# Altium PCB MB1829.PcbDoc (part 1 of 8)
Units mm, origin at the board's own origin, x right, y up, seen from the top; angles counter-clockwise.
Board outline 90 x 110 mm, 6 copper layers (Top Layer, Signal Layer 1, Signal Layer 2, Signal Layer 3, Signal Layer 4, Bottom Layer), stack 1.578 mm thick; 466 components, 354 nets, 2058 pads, 1522 vias.
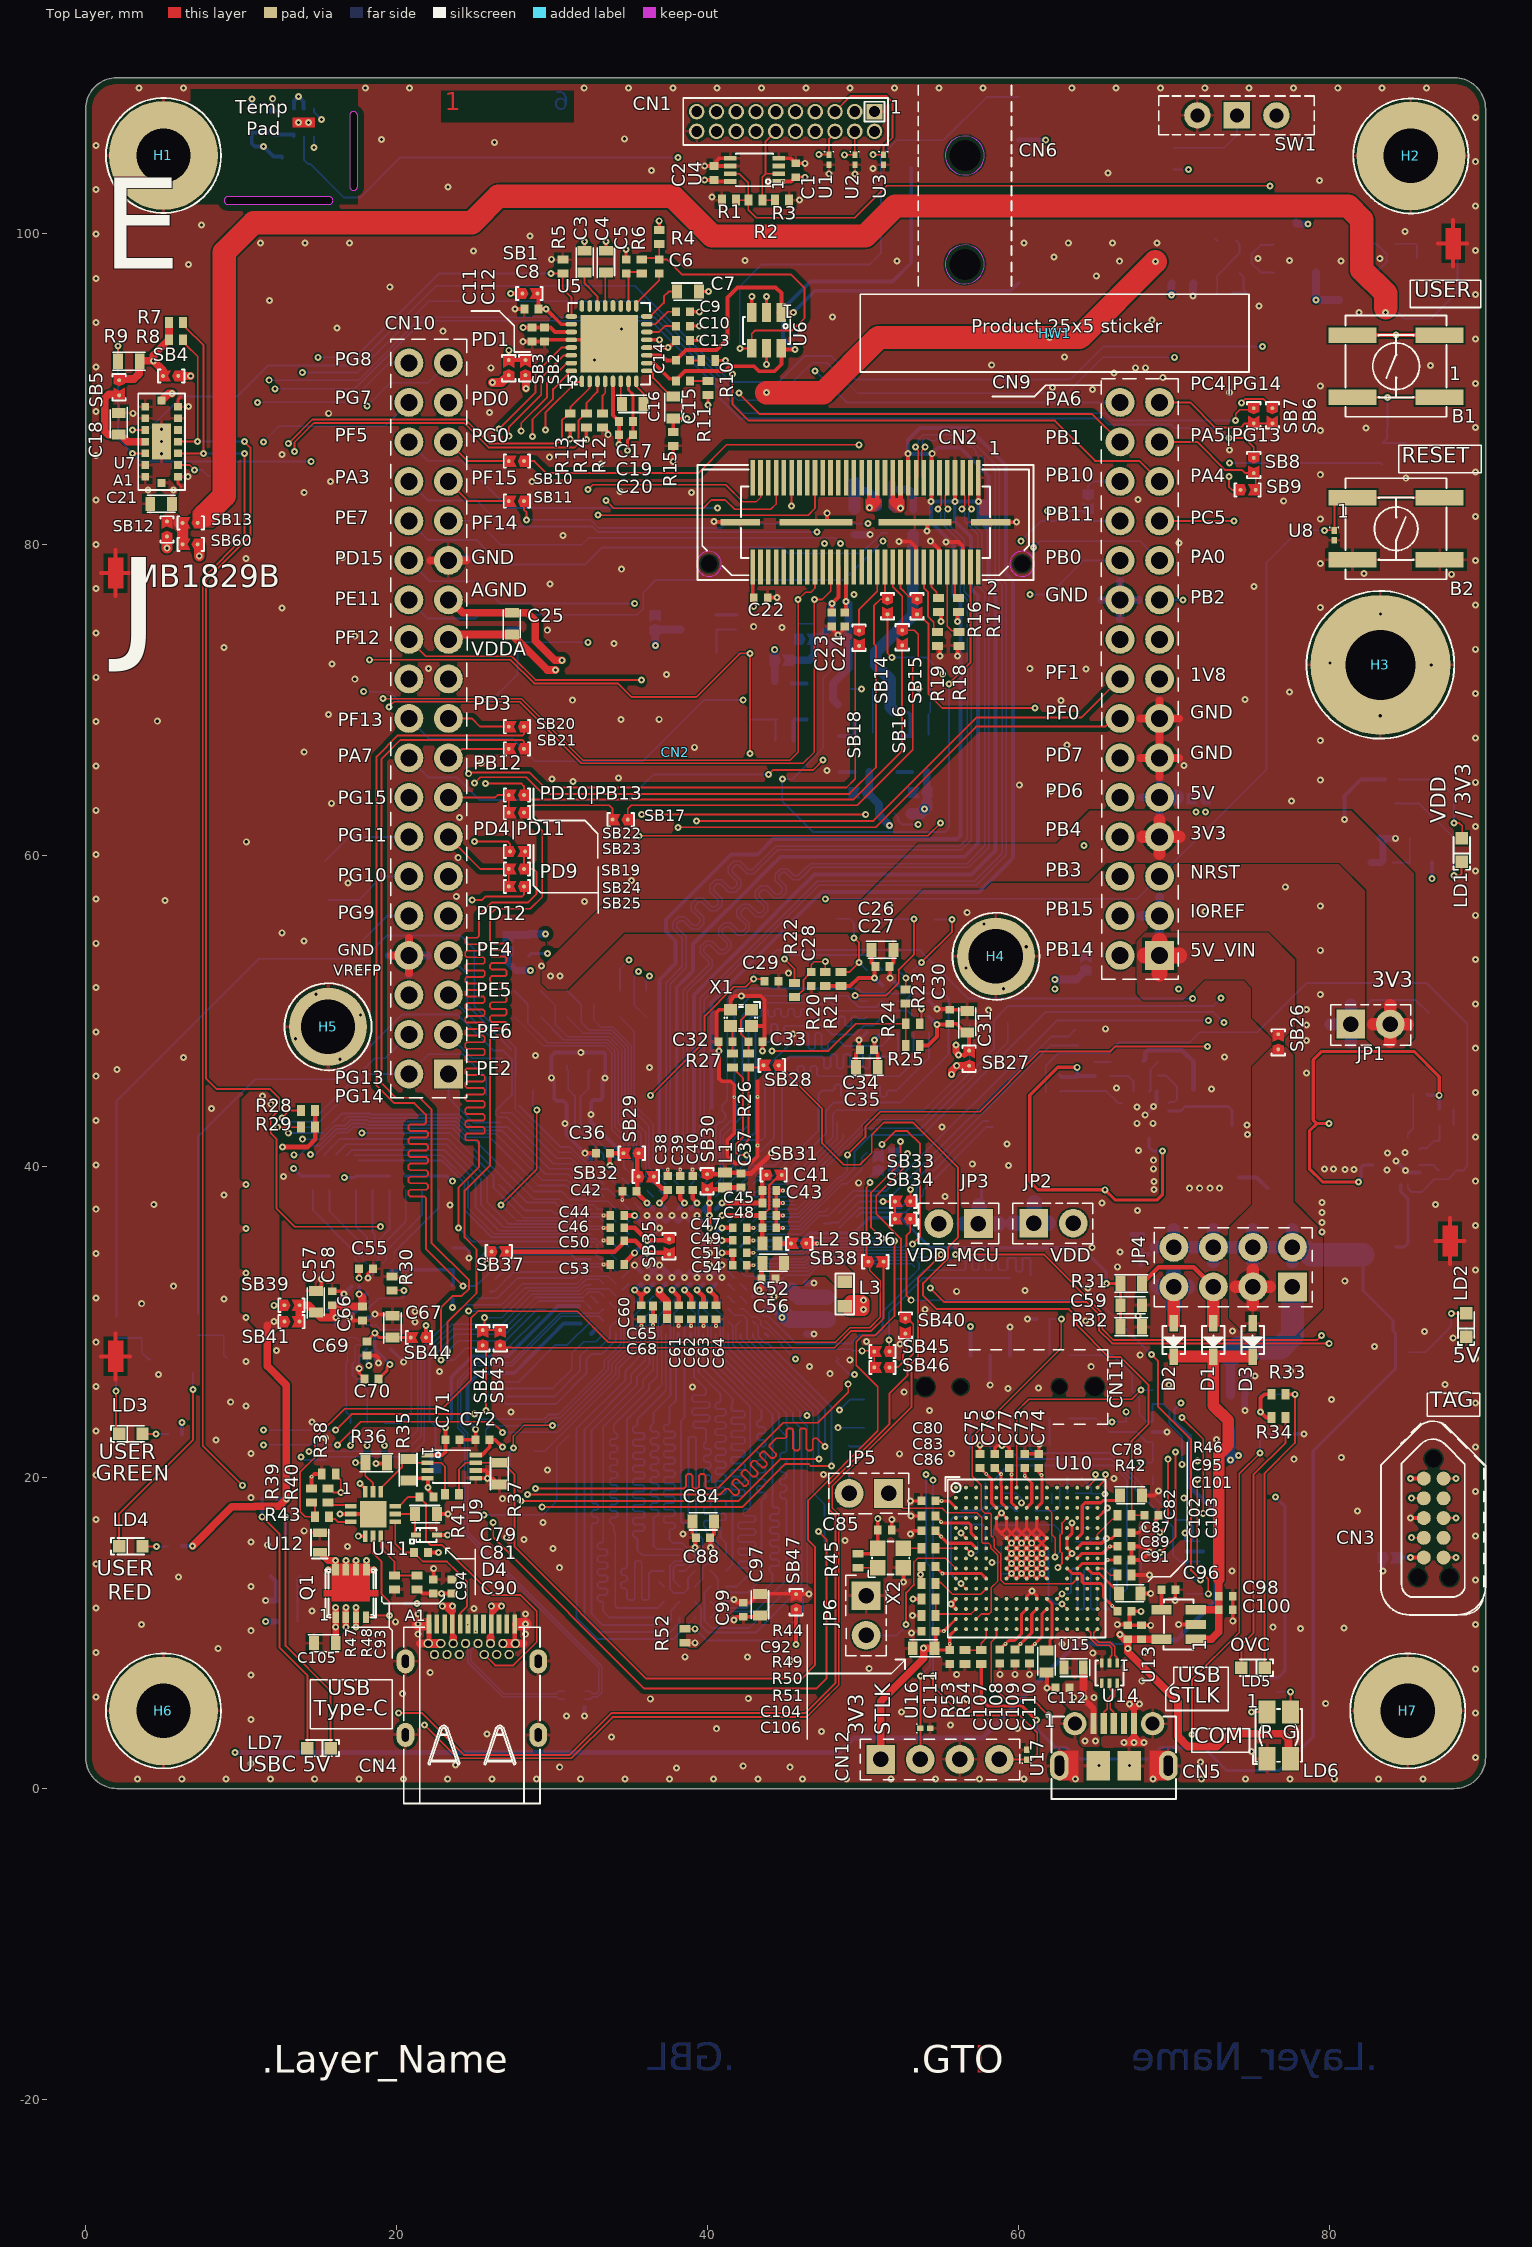
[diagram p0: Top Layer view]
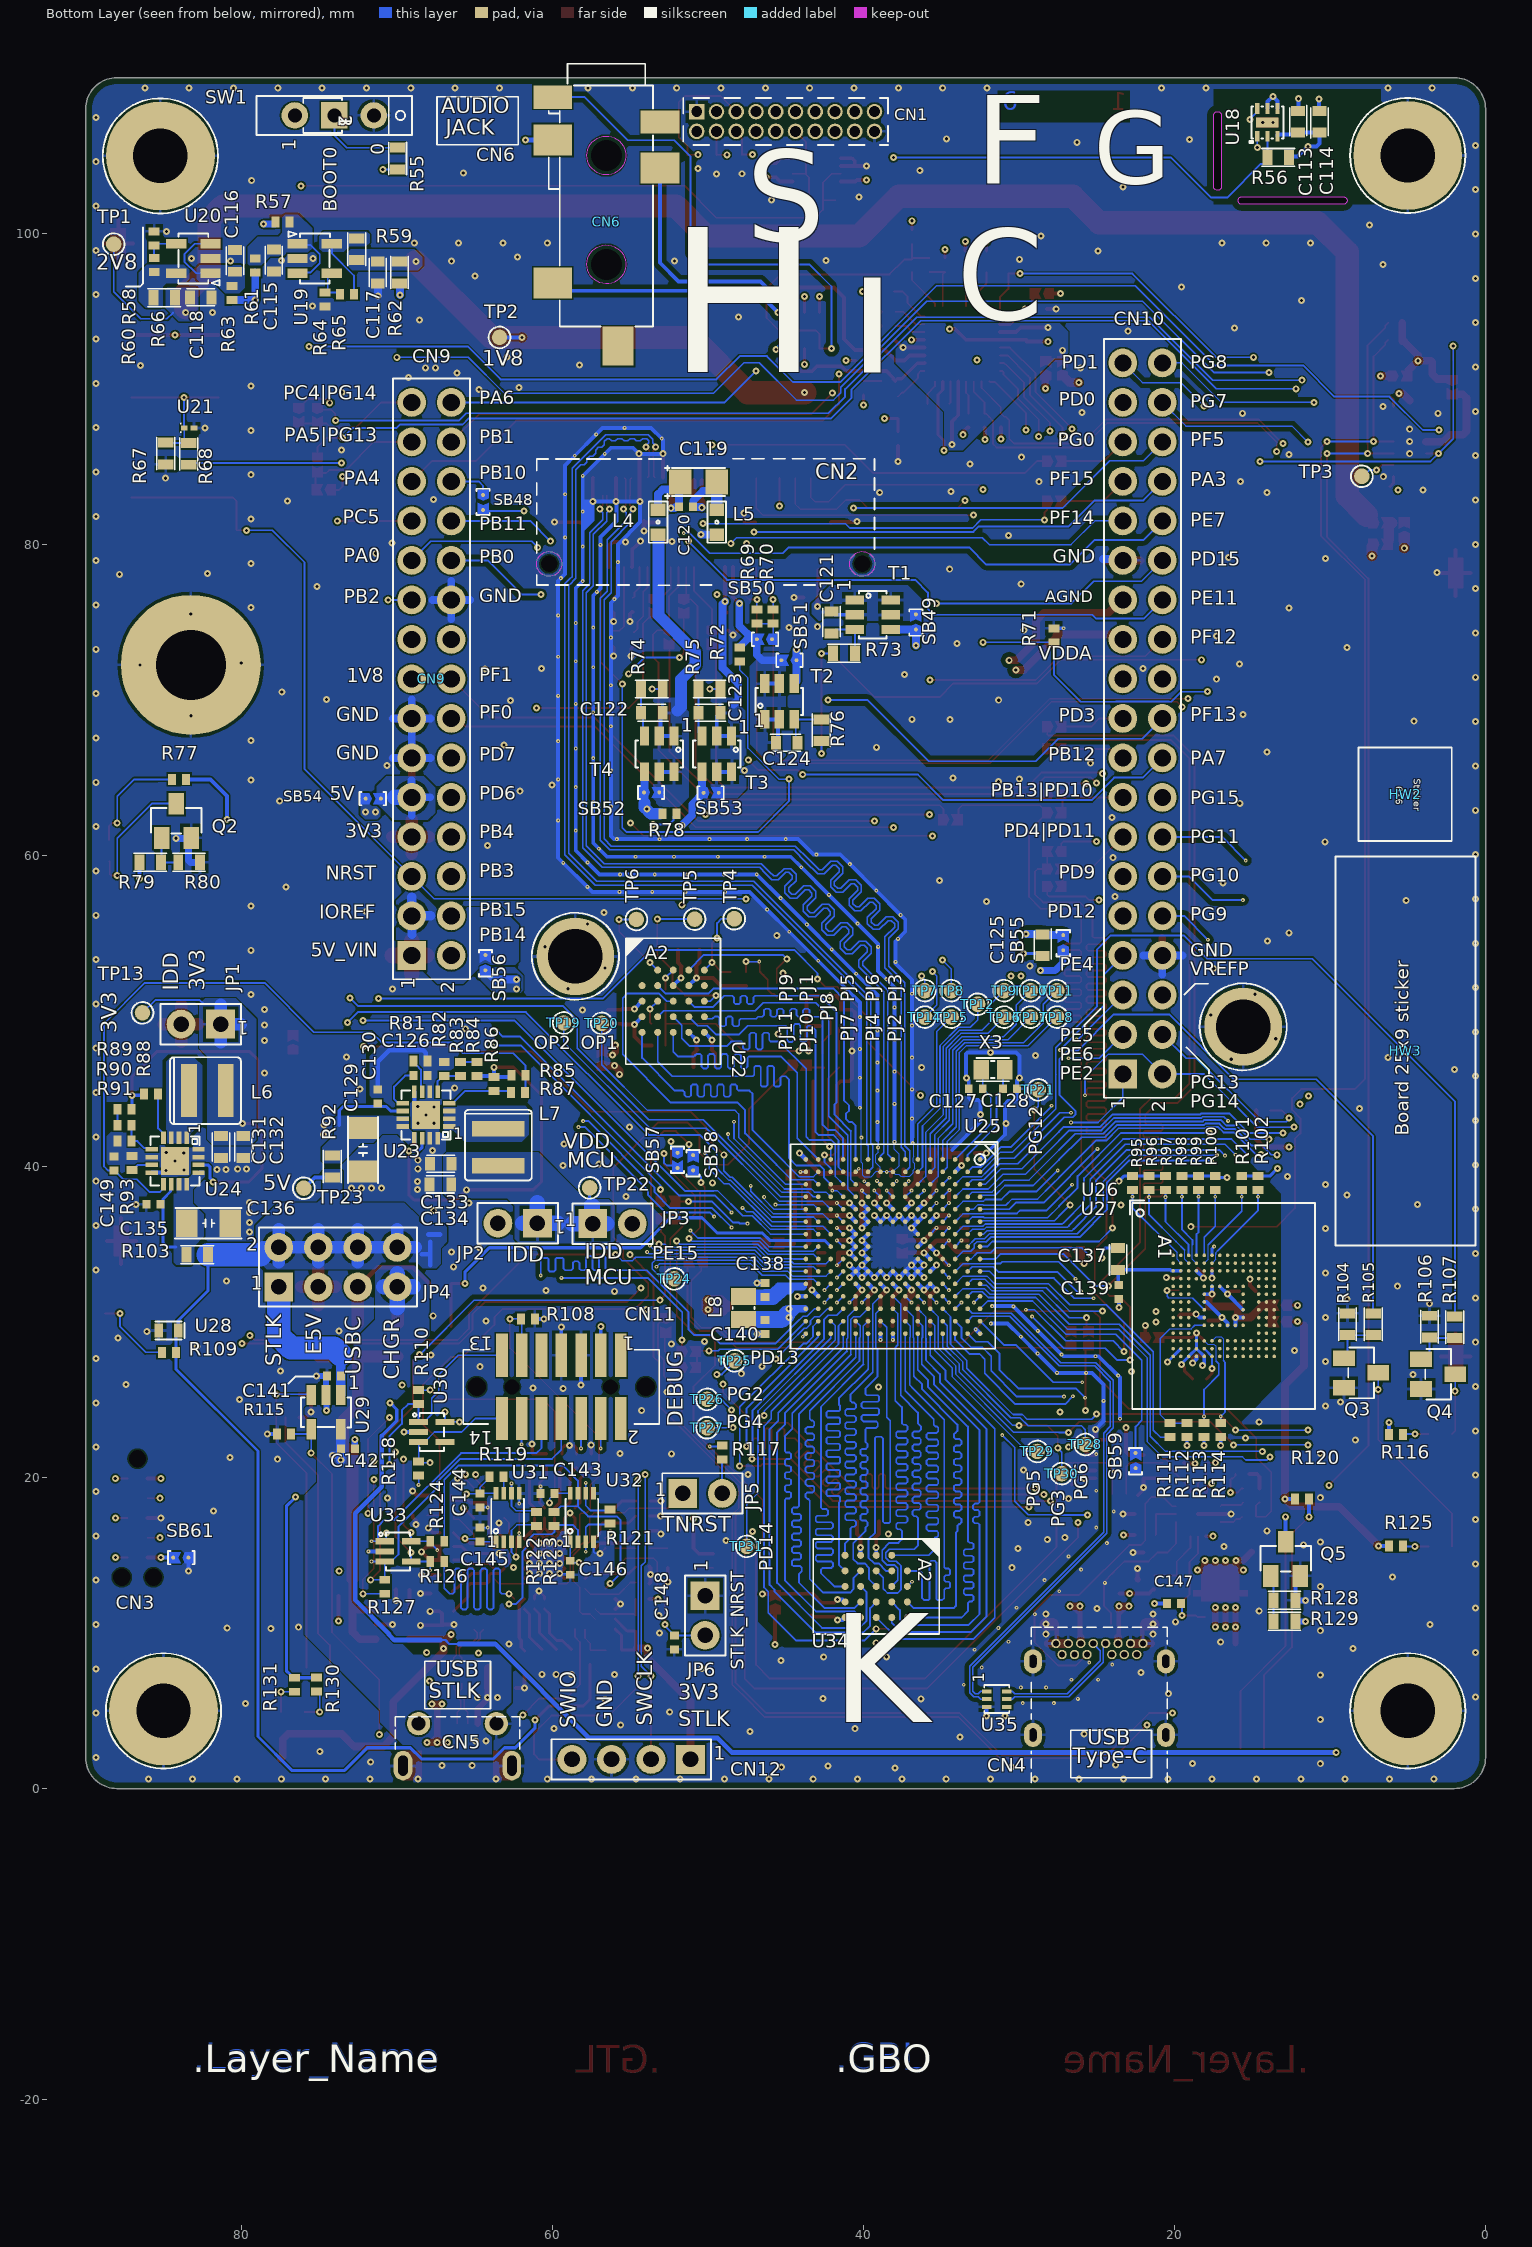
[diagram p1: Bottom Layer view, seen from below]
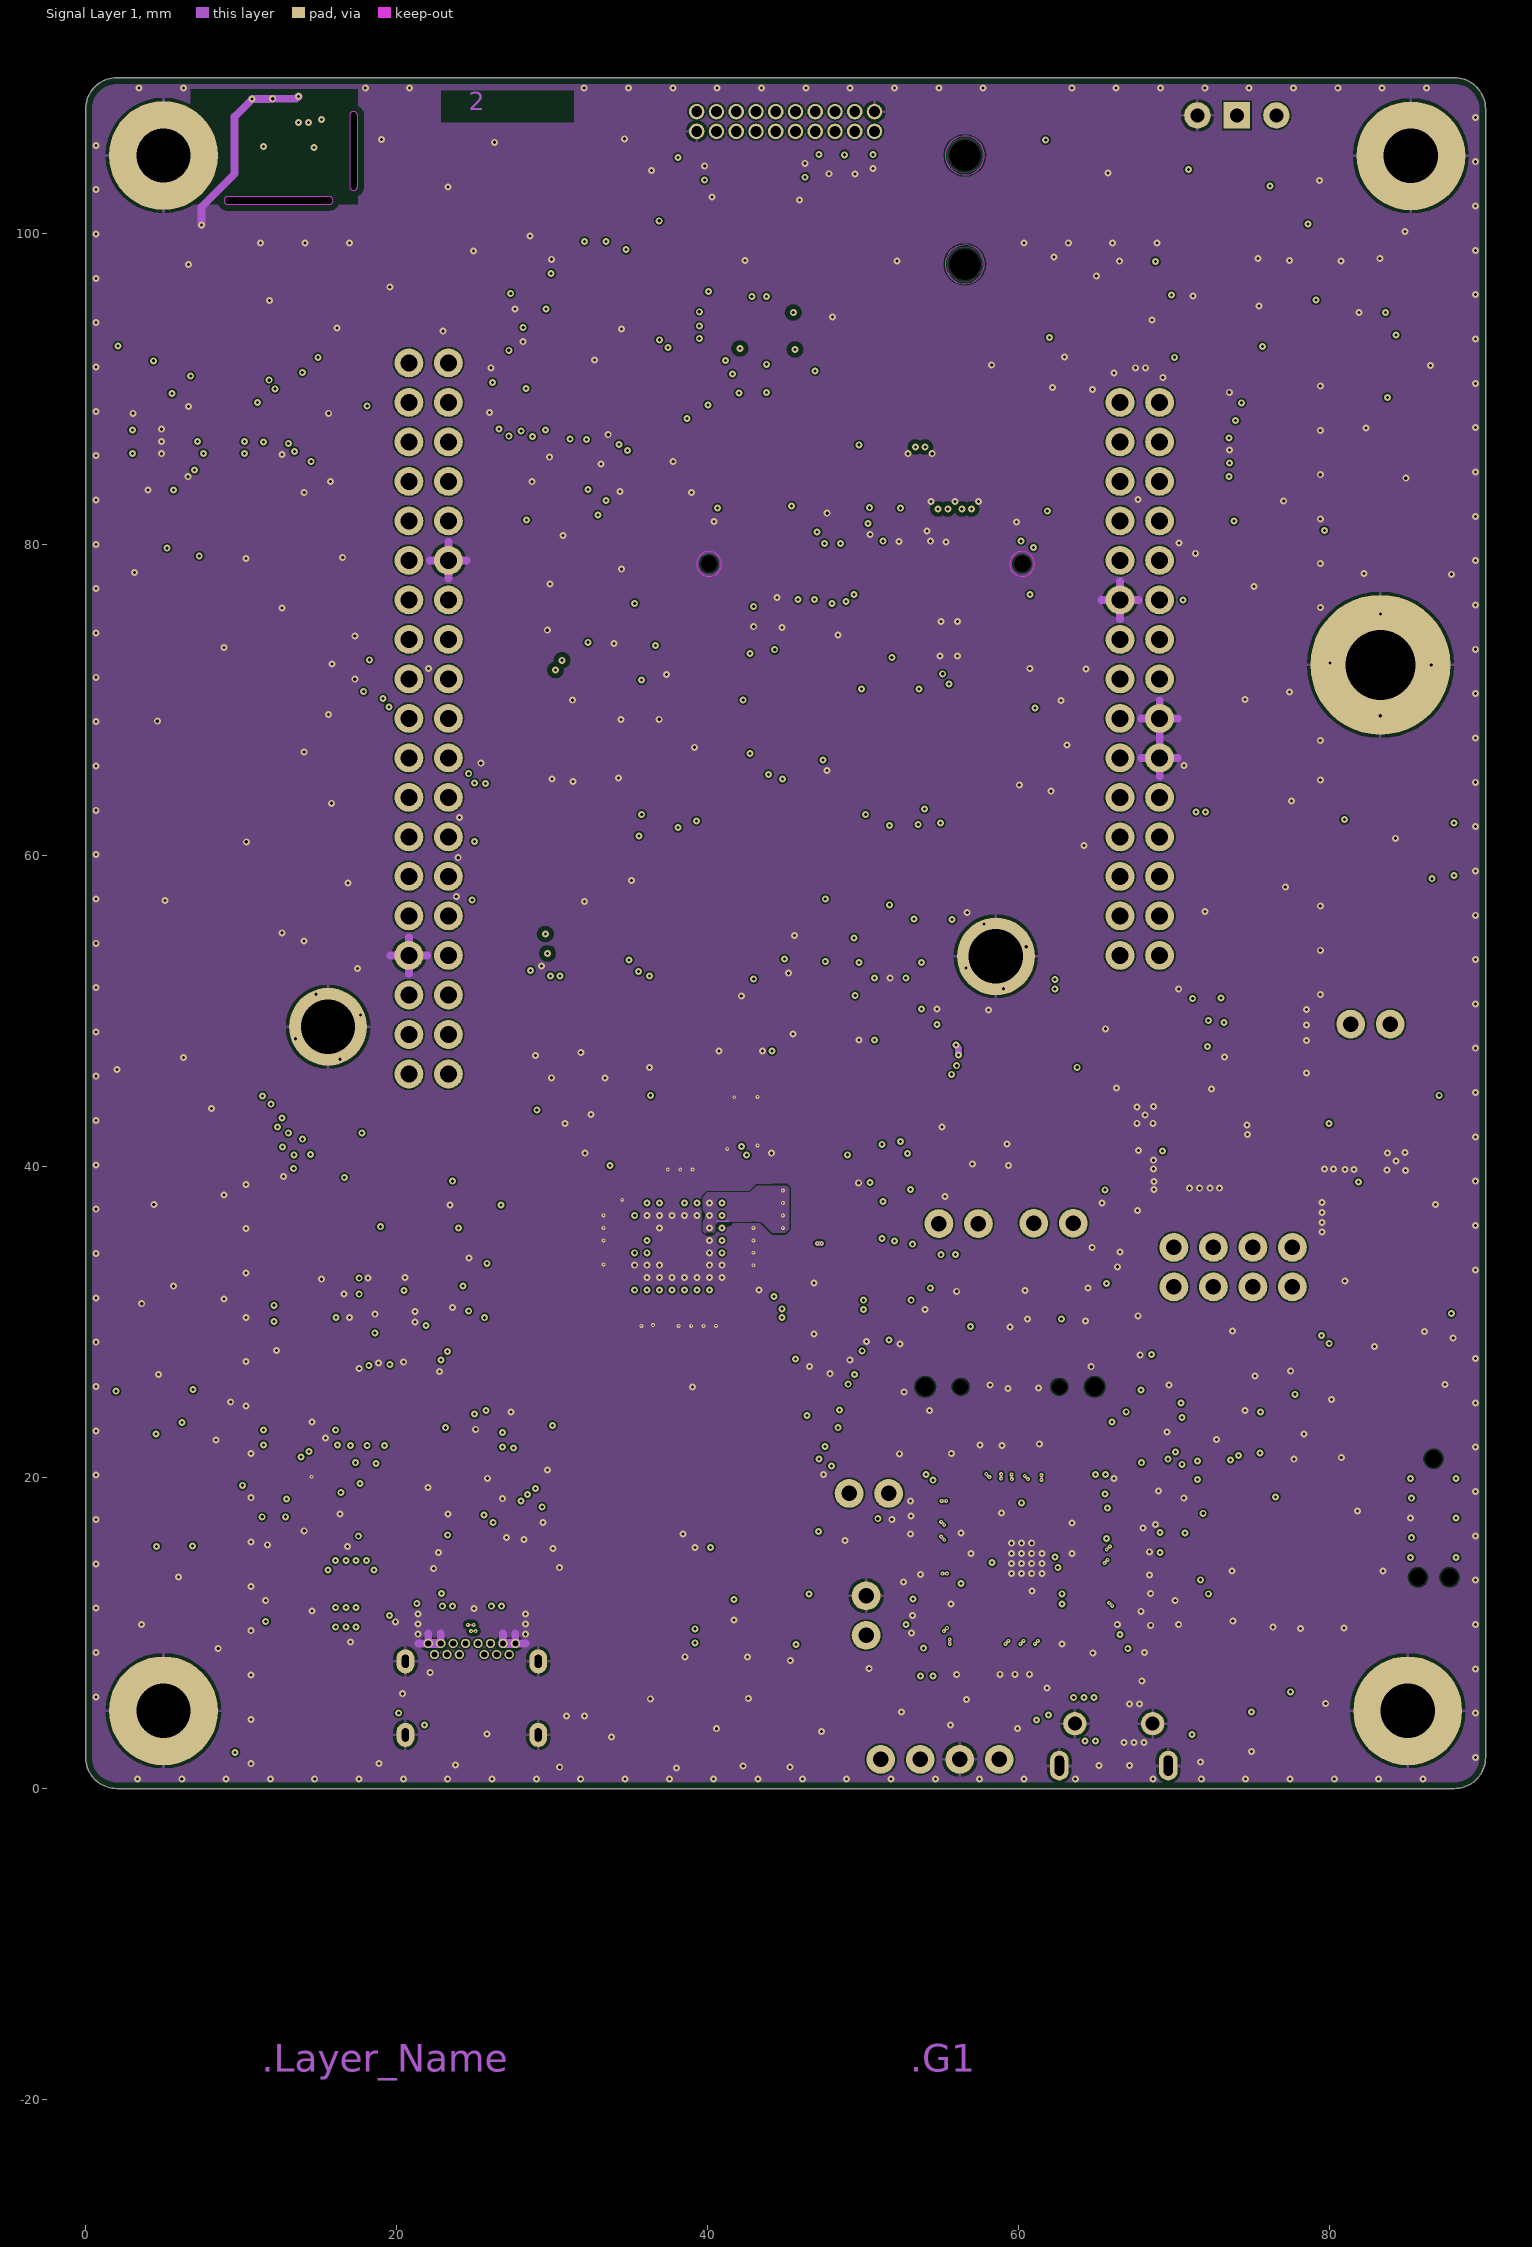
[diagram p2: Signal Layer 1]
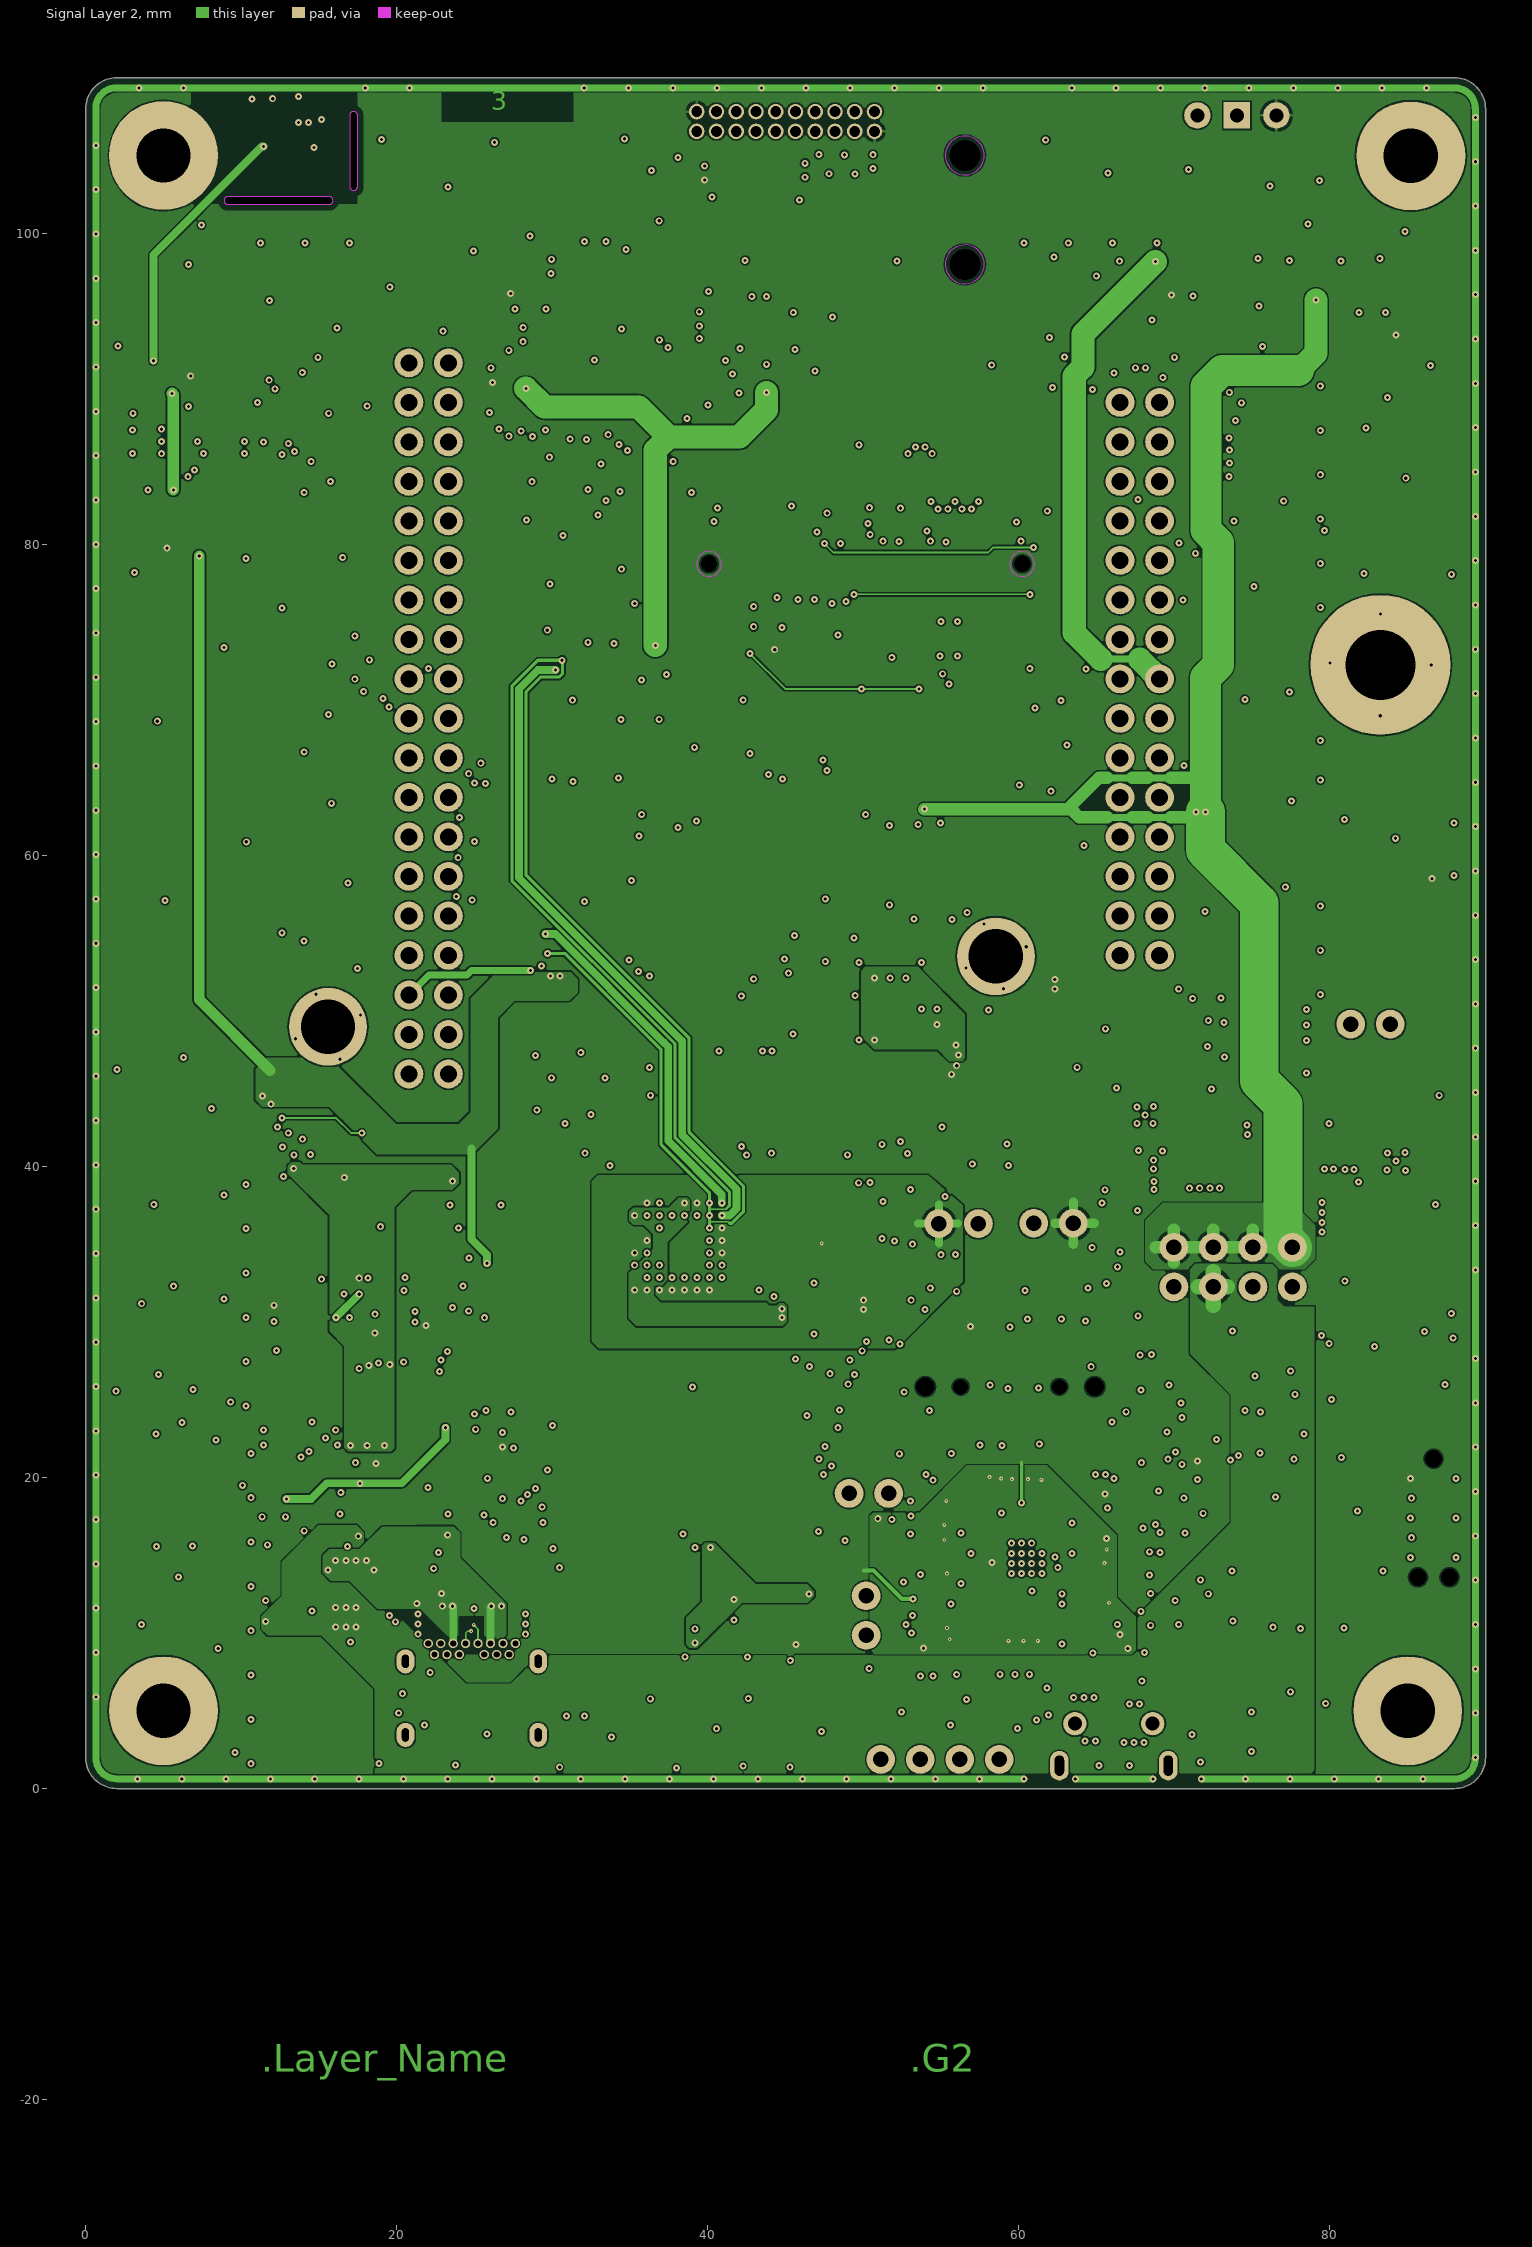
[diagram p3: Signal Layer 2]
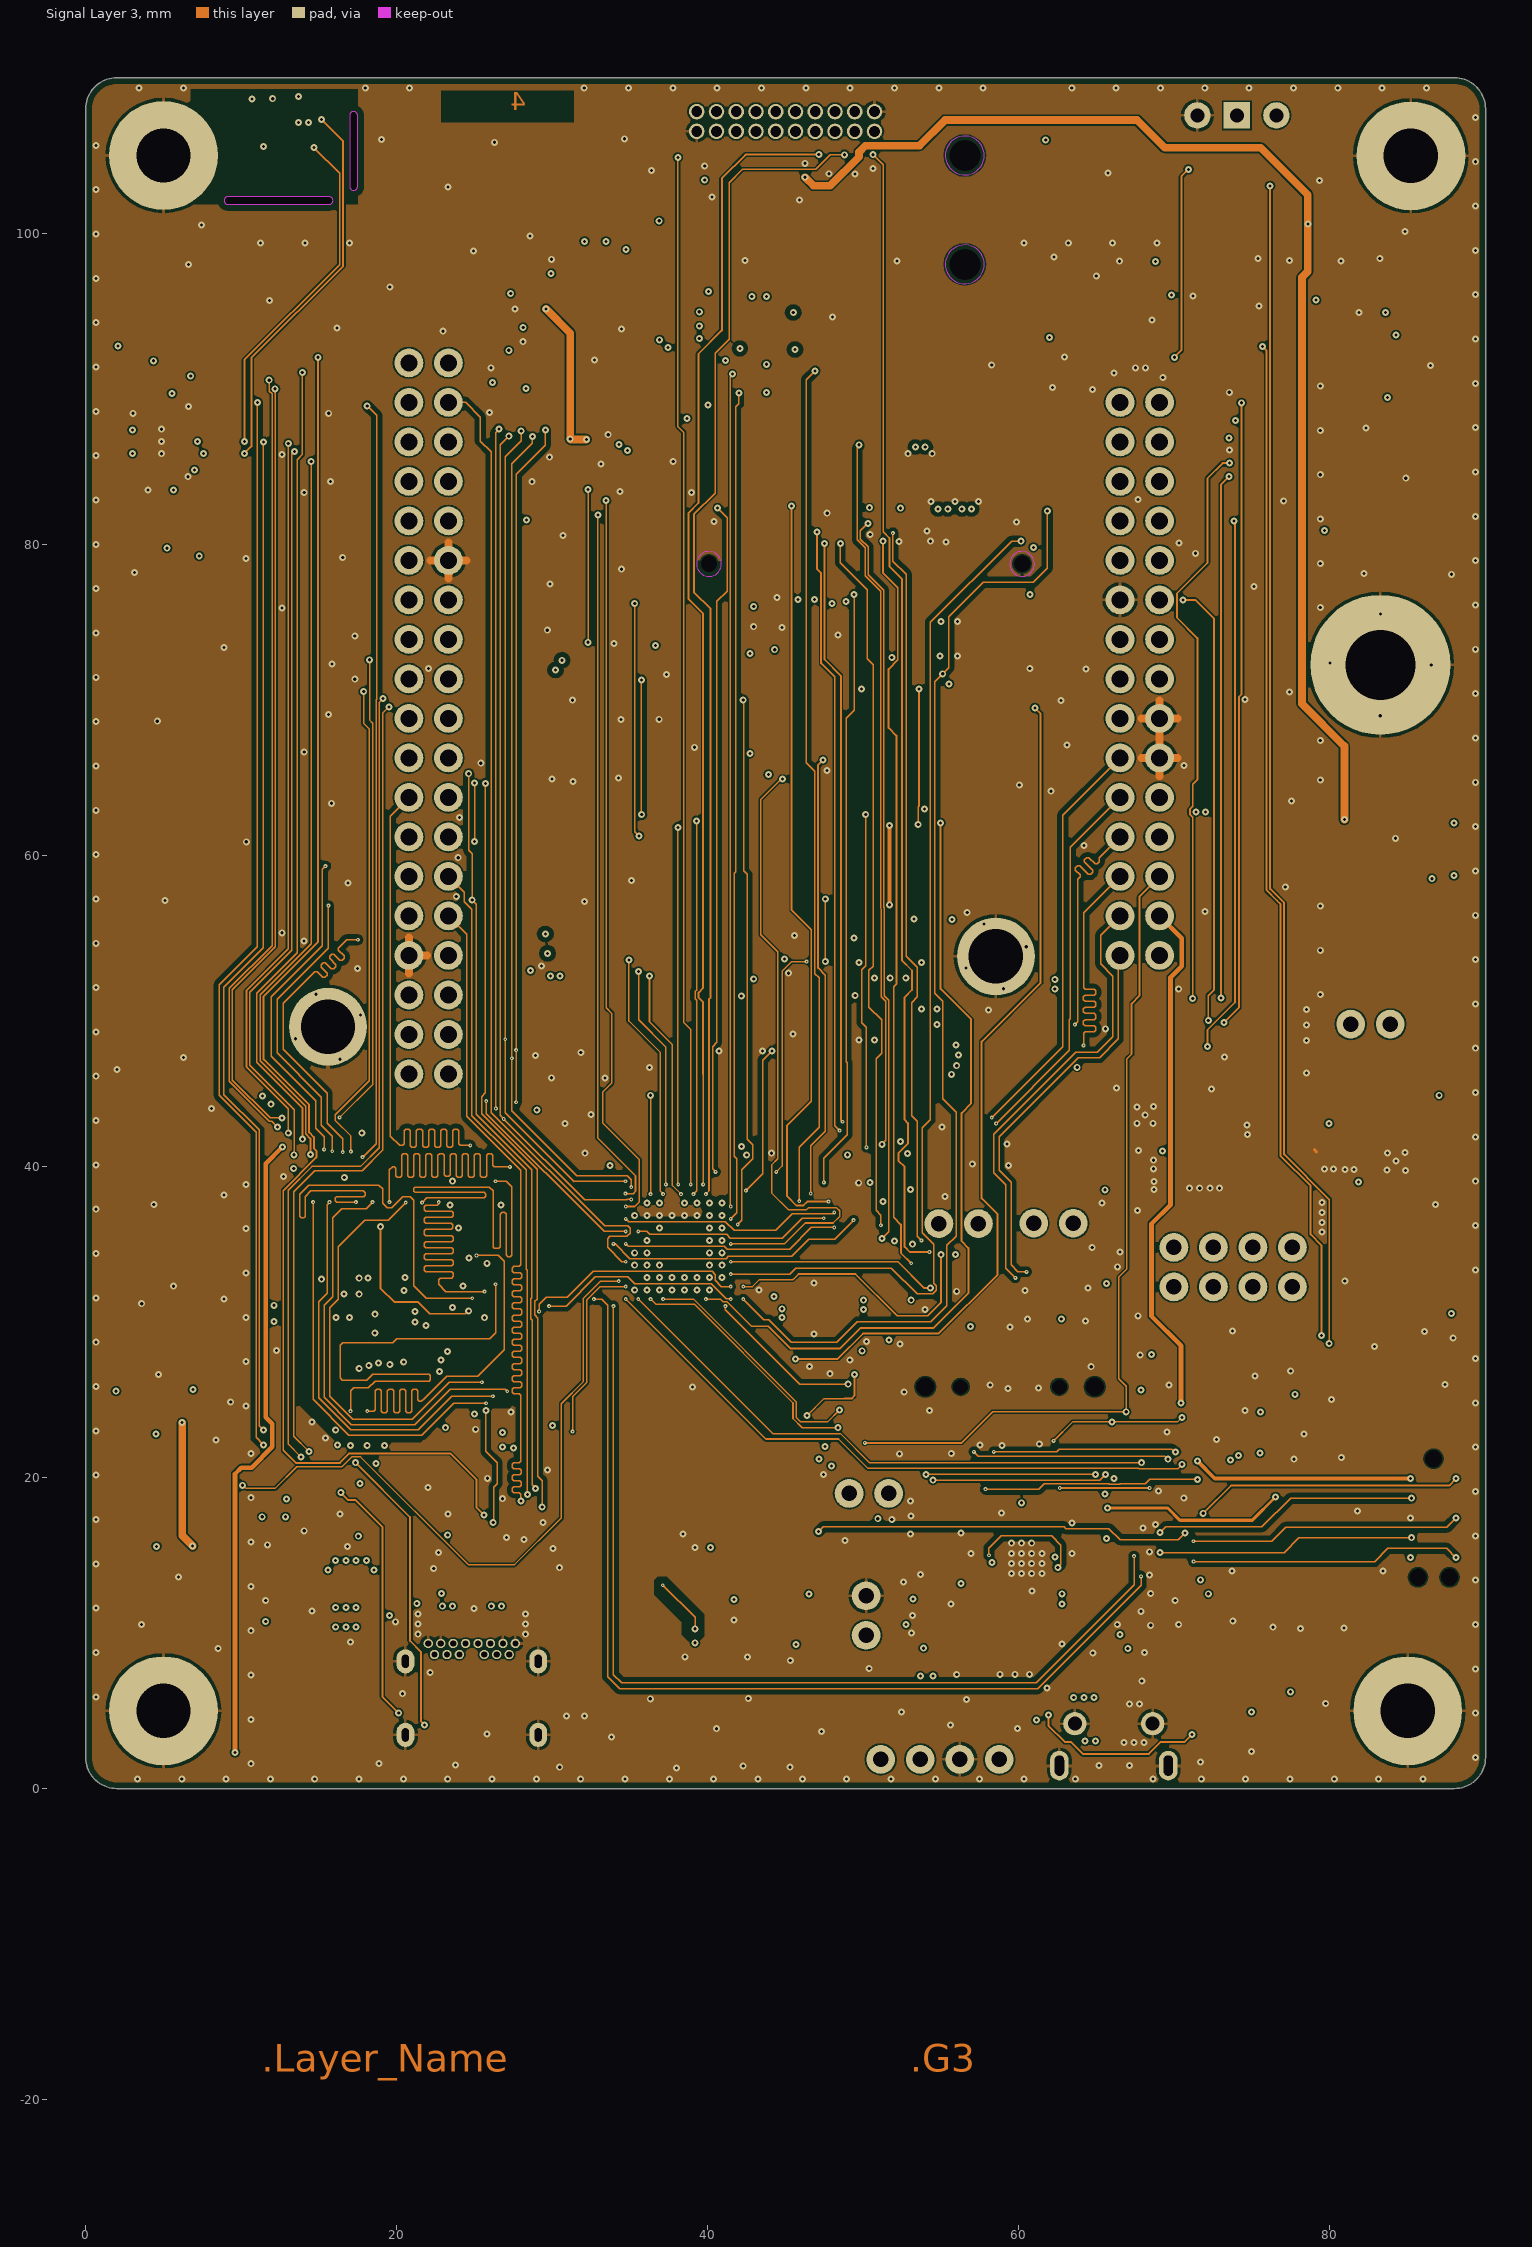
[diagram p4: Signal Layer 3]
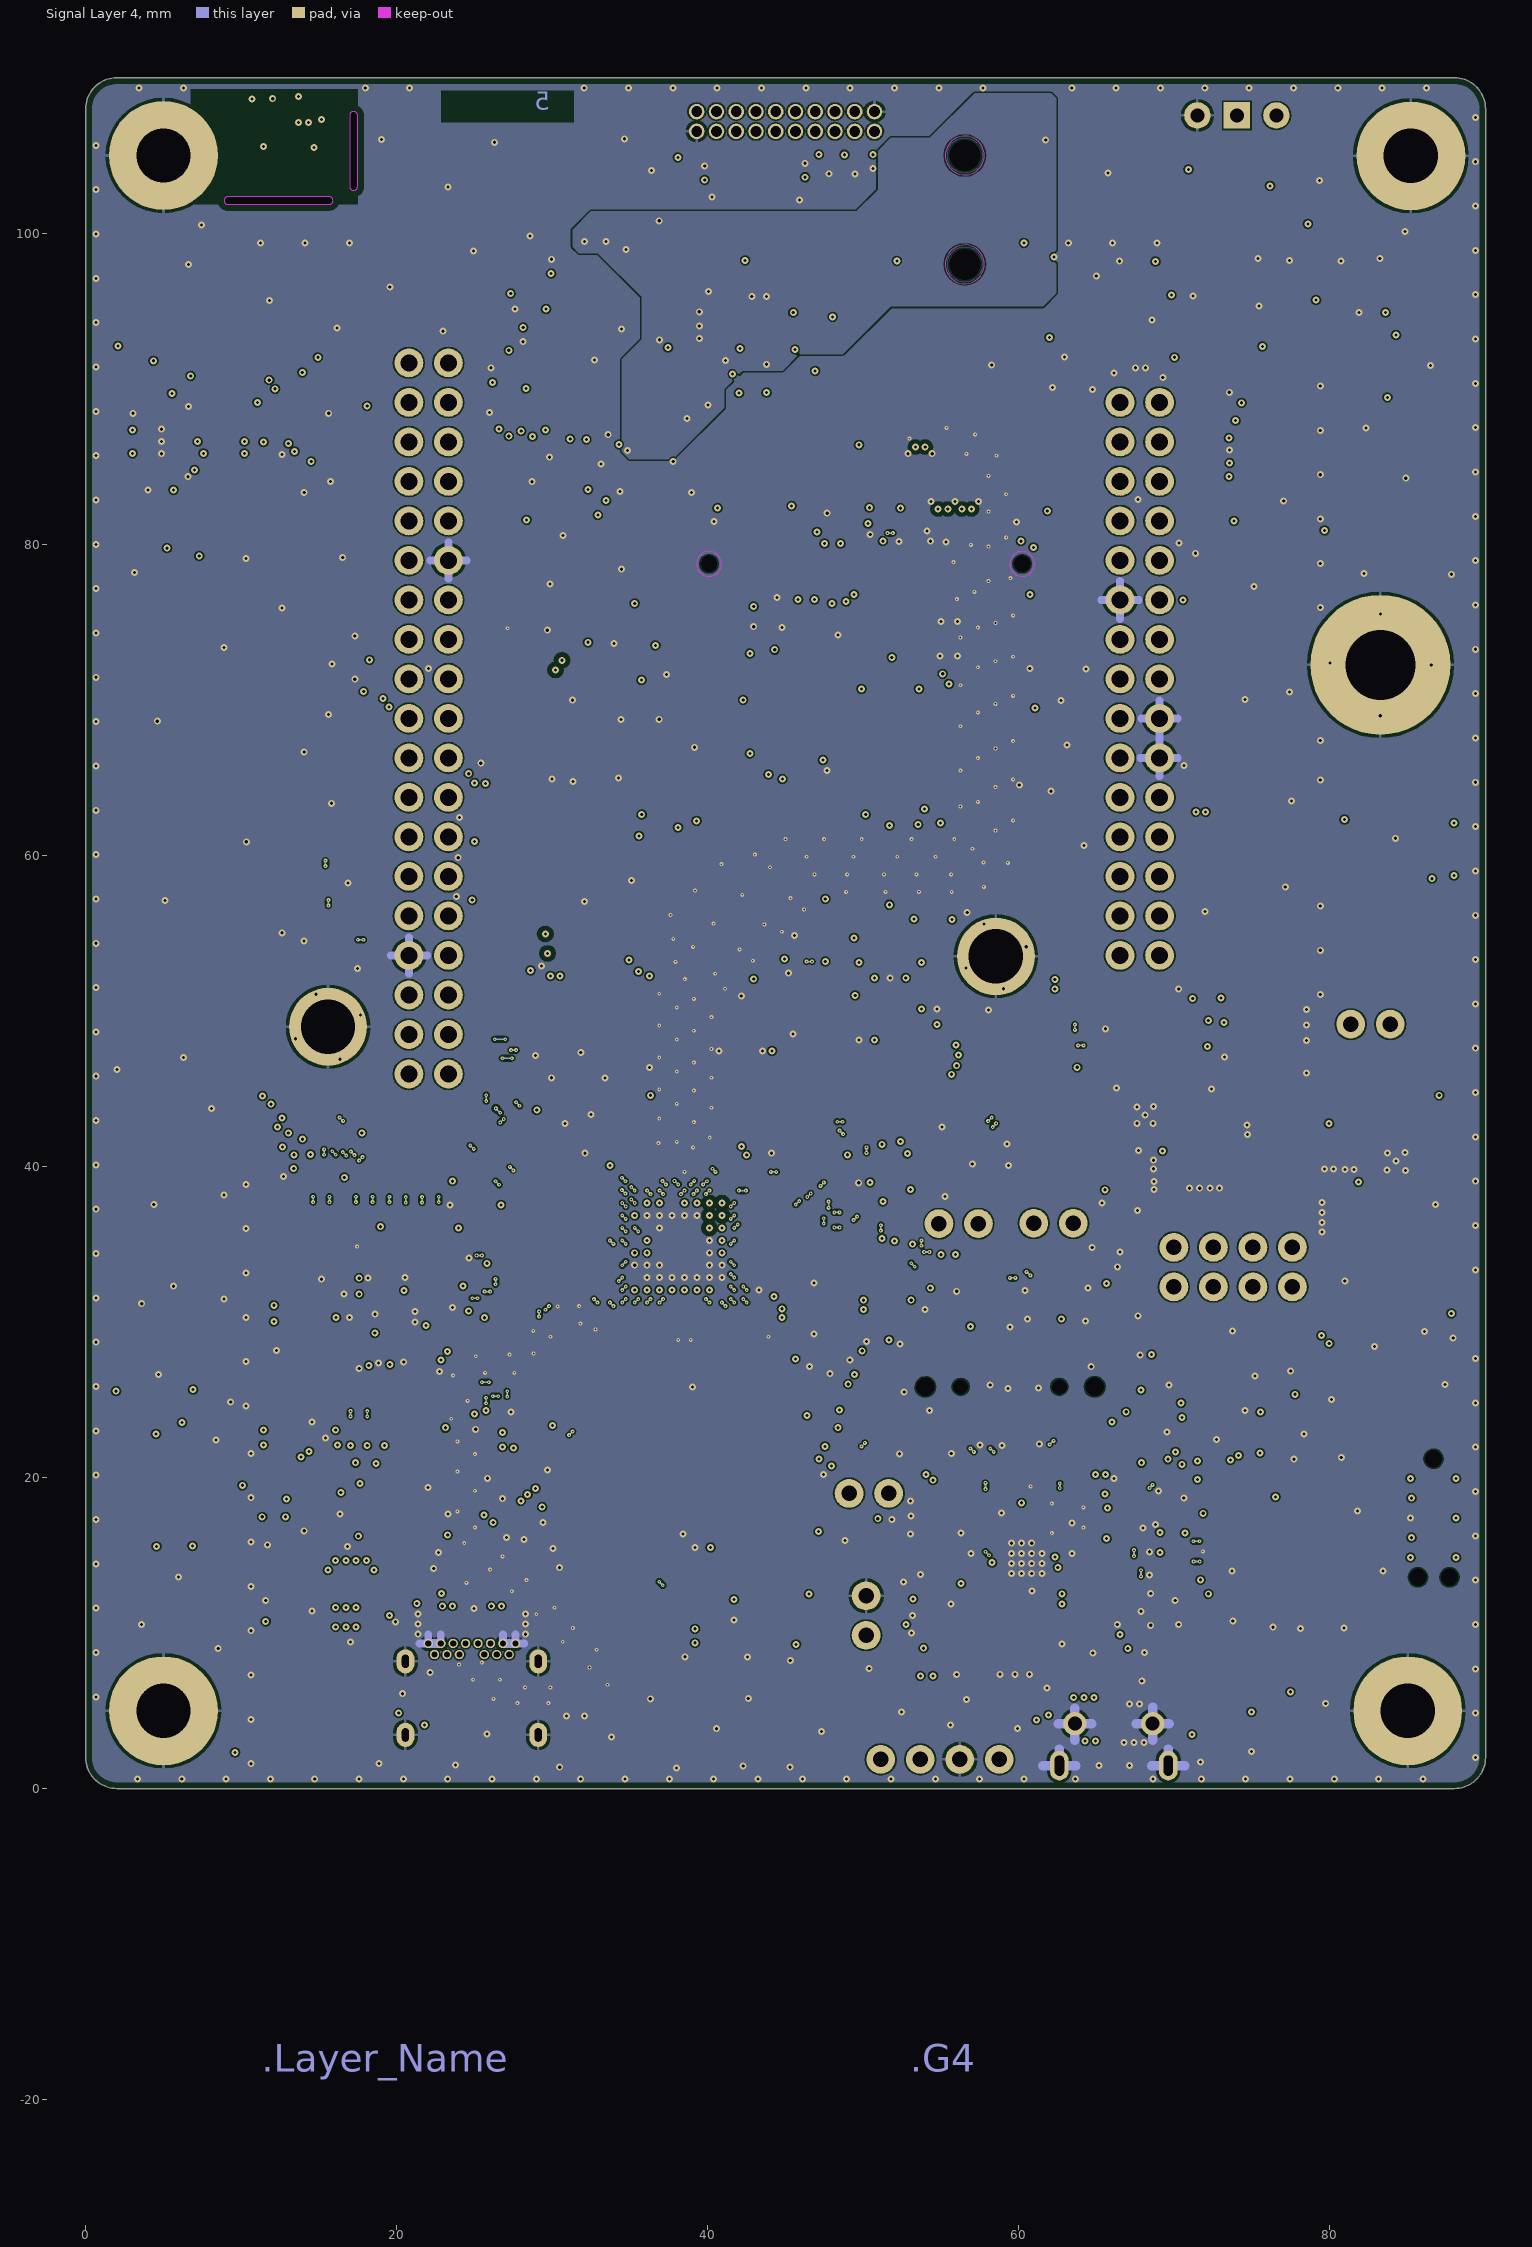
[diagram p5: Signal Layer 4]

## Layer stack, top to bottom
Top Solder: solder mask 0.015, Solder Resist, Dk 3.5
Top Layer: signal copper 0.042
Dielectric 1: dielectric 0.076, 1080HR RC68, Dk 4.2
Signal Layer 1: signal copper 0.035
Dielectric3: dielectric 0.076, 1080HR RC68, Dk 4.2
Signal Layer 2: signal copper 0.035
Dielectric4: dielectric 1.05, FR-4, Dk 4.2
Signal Layer 3: signal copper 0.035
Dielectric5: dielectric 0.076, 1080HR RC68, Dk 4.2
Signal Layer 4: signal copper 0.035
Dielectric2: dielectric 0.076, 1080HR RC68, Dk 4.2
Bottom Layer: signal copper 0.042
Bottom Solder: solder mask 0.015, Solder Resist, Dk 3.5

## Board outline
0,2 0,108 cw(c2,108) 2,110 88,110 cw(c88,108) 90,108 90,2 cw(c88,2) 88,0 2,0 cw(c2,2)
cut-out: 16.975,103.025 ccw(c17.25,103.025) 17.25,102.75 ccw(c17.225,103) 17.475,103.025 17.475,107.575 ccw(c17.225,107.575) 17.225,107.825 ccw(c17.225,107.575) 16.975,107.575
cut-out: 9.15,101.85 15.65,101.85 ccw(c15.65,102.1) 15.9,102.1 ccw(c15.65,102.1) 15.65,102.35 9.15,102.35 ccw(c9.15,102.1) 8.9,102.1 ccw(c9.15,102.1)

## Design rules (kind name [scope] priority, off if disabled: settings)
BoardOutlineClearance [All] p1: gap=0.4 ignorepadtopadclearanceinfootprint=FALSE except(0: Arc-SplitContinuation Track-SplitContinuation SMDPad-SplitContinuation THPad-SplitContinuation Via-SplitContinuation Fill-SplitContinuation Poly-SplitContinuation Region-SplitContinuation Text-SplitContinuation)
Clearance "Clearance L6&L7" [InNet('NetL6_1') or   InNet('NetL7_1') vs InNet('GND')] p1: gap=0.1 ignorepadtopadclearanceinfootprint=FALSE except(0: Arc-Hole Track-Hole SMDPad-Hole THPad-Hole Via-Hole Fill-Hole Poly-Hole Region-Hole Text-Hole; 0.25: Arc-Fill Arc-Poly Arc-Region Track-Fill Track-Poly Track-Region SMDPad-Fill SMDPad-Poly SMDPad-Region THPad-Fill THPad-Poly THPad-Region Via-Fill Via-Poly Via-Region Fill-Fill Fill-Poly Fill-Region Poly-Poly Poly-Region Region-Region)
Clearance Clearance_USB [InNetClass('USB High Speed') vs InNet('GND')] p2: gap=0.1 ignorepadtopadclearanceinfootprint=FALSE except(0: Arc-Hole Track-Hole SMDPad-Hole THPad-Hole Via-Hole Fill-Hole Poly-Hole Region-Hole Text-Hole; 0.25: Arc-Arc Arc-Track Track-Track Track-Poly)
Clearance Clearance_DSI [InNetClass('DSI') vs InNet('GND')] p3: gap=0.1 ignorepadtopadclearanceinfootprint=FALSE except(0: Arc-Hole Track-Hole SMDPad-Hole THPad-Hole Via-Hole Fill-Hole Poly-Hole Region-Hole Text-Hole; 0.27: Arc-Arc Arc-Track Track-Track Track-Poly Via-Poly)
Clearance Clearance_50Ohms_GND_L5 [InNetClass('50Ohms') vs OnLayer('Signal Layer 4')] p4: gap=0.1 ignorepadtopadclearanceinfootprint=FALSE except(0: Arc-Hole Track-Hole SMDPad-Hole THPad-Hole Via-Hole Fill-Hole Poly-Hole Region-Hole Text-Hole; 0.175: Track-Poly; 0.3: Arc-Arc Arc-Track Track-Track)
Clearance Clearance_50Ohms_GND [InNetClass('50Ohms') vs InNet('GND')] p5: gap=0.1 ignorepadtopadclearanceinfootprint=FALSE except(0: Arc-Hole Track-Hole SMDPad-Hole THPad-Hole Via-Hole Fill-Hole Poly-Hole Region-Hole Text-Hole; 0.3: Arc-Arc Arc-Track Track-Track Track-Poly)
Clearance Clearance_audio_GND [InNetClass('Audio') vs InNet('GND')] p6: gap=0.1 ignorepadtopadclearanceinfootprint=FALSE except(0: Arc-Hole Track-Hole SMDPad-Hole THPad-Hole Via-Hole Fill-Hole Poly-Hole Region-Hole Text-Hole; 0.3: Arc-Arc Arc-Track Track-Track Track-Poly Via-Poly)
Clearance Clearance_BGA_MCU_HexaSPI_1 [WithinRoom('RoomDefinition')and TouchesRoom('RoomDefinition')] p7: gap=0.1 ignorepadtopadclearanceinfootprint=FALSE except(0: Arc-Hole Track-Hole SMDPad-Hole THPad-Hole Via-Hole Fill-Hole Poly-Hole Region-Hole Text-Hole)
Clearance Clearance_BGA_STLink [WithinRoom('RoomDefinition_1')and TouchesRoom('RoomDefinition_1')] p8: gap=0.085 ignorepadtopadclearanceinfootprint=FALSE except(0: Arc-Hole Track-Hole SMDPad-Hole THPad-Hole Via-Hole Fill-Hole Poly-Hole Region-Hole Text-Hole; 0.1: Arc-Poly Track-Poly SMDPad-Poly THPad-Poly Via-Poly Fill-Poly Poly-Poly)
Clearance Clearance_AGND_VREFP_VDDA [InNetClass('VREFP_AGND_VDDA') vs InNet('GND')] p9: gap=0.1 ignorepadtopadclearanceinfootprint=FALSE except(0: Arc-Hole Track-Hole SMDPad-Hole THPad-Hole Via-Hole Fill-Hole Poly-Hole Region-Hole Text-Hole; 0.3: Track-Poly Via-Poly)
Clearance Clearance_USB_L5 [OnLayer('Signal Layer 4') vs InNetClass('USB High Speed')] p10: gap=0.1 ignorepadtopadclearanceinfootprint=FALSE except(0: Arc-Hole Track-Hole SMDPad-Hole THPad-Hole Via-Hole Fill-Hole Poly-Hole Region-Hole Text-Hole)
Clearance Clearance_OSC_GND [InNetClass('OSC') vs InNet('GND')] p11: gap=0.1 ignorepadtopadclearanceinfootprint=FALSE except(0: Arc-Hole Track-Hole SMDPad-Hole THPad-Hole Via-Hole Fill-Hole Poly-Hole Region-Hole Text-Hole; 0.36: Arc-Arc Arc-Track Track-Track Track-Poly SMDPad-Poly)
Clearance Clearance_OSC [InNetClass('OSC') vs InNetClass('OSC')] p12: gap=0.1 ignorepadtopadclearanceinfootprint=FALSE except(0: Arc-Hole Track-Hole SMDPad-Hole THPad-Hole Via-Hole Fill-Hole Poly-Hole Region-Hole Text-Hole; 0.24: Arc-Arc Arc-Track Track-Track)
Clearance Clearance_eMMC [WithinRoom('RoomDefinition_2')and TouchesRoom('RoomDefinition_2')] p13: gap=0.085 ignorepadtopadclearanceinfootprint=FALSE except(0: Arc-Hole Track-Hole SMDPad-Hole THPad-Hole Via-Hole Fill-Hole Poly-Hole Region-Hole Text-Hole; 0.1: Arc-Poly Track-Poly SMDPad-Poly THPad-Poly Via-Poly Fill-Poly Poly-Poly)
Clearance Clearance_50Ohms [InNetClass('50Ohms') vs InNetClass('50Ohms')] p14: gap=0.1 ignorepadtopadclearanceinfootprint=FALSE except(0: Arc-Hole Track-Hole SMDPad-Hole THPad-Hole Via-Hole Fill-Hole Poly-Hole Region-Hole Text-Hole)
Clearance [All] p15: gap=0.1 ignorepadtopadclearanceinfootprint=FALSE except(0: Arc-Hole Track-Hole SMDPad-Hole THPad-Hole Via-Hole Fill-Hole Poly-Hole Region-Hole Text-Hole)
ComponentClearance [All] p1: gap=0.05 collisioncheckmode=3 verticalgap=0.1 showdistances=FALSE
DiffPairsRouting DiffPairsRouting_90Ohms [InDifferentialPairClass('USB')] p1: maxlimit=0.254 minlimit=0.1 mostfreqgap=0.127 toplayer_maxgap=0.1 toplayer_prefgap=0.1 toplayer_minwidth=0.095 toplayer_maxwidth=0.095 toplayer_prefwidth=0.095 bottomlayer_maxgap=0.1 bottomlayer_prefgap=0.1 bottomlayer_minwidth=0.095 bottomlayer_maxwidth=0.095 bottomlayer_prefwidth=0.095 impedanceprofiledriven=TRUE impedanceprofileid={B1AB549F-53D4-4C69-843F-679EAB43666C} impedanceprofilevalue=90.000000 maxuncoupledlength=12.7
DiffPairsRouting DiffPairsRouting_100Ohms [InDifferentialPairClass('DSI')] p2: maxlimit=0.254 minlimit=0.127 mostfreqgap=0.254 toplayer_mingap=0.16 toplayer_maxgap=0.16 toplayer_prefgap=0.16 toplayer_minwidth=0.09 toplayer_maxwidth=0.09 toplayer_prefwidth=0.09 midlayer2_maxgap=0.127 midlayer2_prefgap=0.127 midlayer2_minwidth=0.044 midlayer2_maxwidth=0.044 midlayer2_prefwidth=0.044 midlayer3_maxgap=0.127 midlayer3_prefgap=0.127 midlayer3_minwidth=0.044 midlayer3_maxwidth=0.044 midlayer3_prefwidth=0.044 bottomlayer_mingap=0.16 bottomlayer_maxgap=0.16 bottomlayer_prefgap=0.16 bottomlayer_minwidth=0.09 bottomlayer_maxwidth=0.09 bottomlayer_prefwidth=0.09 impedanceprofiledriven=TRUE impedanceprofileid={B2E96355-3B74-4573-B774-3E88F903998F} impedanceprofilevalue=100.000000 maxuncoupledlength=12.7
HoleSize [All] p1: absolutevalues=TRUE maxlimit=10 minlimit=0.025 maxpercent=80.000 minpercent=20.000
HoleToHoleClearance [All] p1: gap=0.2 allowstackedmicrovias=TRUE
MatchedLengths "Schematic Matched Net Lengths_55" [InNet('HEXASPI1.NCS')] p1: tolerance=25.4 checknetsindiffpair=FALSE checkdiffpairvsdiffpair=TRUE checkxsignals=TRUE checkothers=TRUE
MatchedLengths "Schematic Matched Net Lengths_54" [InNet('OCTOSPIM_P1.NCS')] p2: tolerance=25.4 checknetsindiffpair=FALSE checkdiffpairvsdiffpair=TRUE checkxsignals=TRUE checkothers=TRUE
MatchedLengths "Schematic Matched Net Lengths_53" [InNet('OCTOSPIM_P1.NCS')] p3: tolerance=12.7 checknetsindiffpair=FALSE checkdiffpairvsdiffpair=TRUE checkxsignals=TRUE checkothers=TRUE
MatchedLengths "Schematic Matched Net Lengths_52" [InNet('SDMMC1.CMD')] p4: tolerance=1.27 checknetsindiffpair=FALSE checkdiffpairvsdiffpair=TRUE checkxsignals=TRUE checkothers=TRUE
MatchedLengths "Schematic Matched Net Lengths_51" [InNet('SDMMC1.D4')] p5: tolerance=0.508 checknetsindiffpair=FALSE checkdiffpairvsdiffpair=TRUE checkxsignals=TRUE checkothers=TRUE
MatchedLengths "Schematic Matched Net Lengths_50" [InNet('SDMMC1.D5')] p6: tolerance=0.508 checknetsindiffpair=FALSE checkdiffpairvsdiffpair=TRUE checkxsignals=TRUE checkothers=TRUE
MatchedLengths "Schematic Matched Net Lengths_49" [InNet('HEXASPI1.IO2')] p7: tolerance=0.508 checknetsindiffpair=FALSE checkdiffpairvsdiffpair=TRUE checkxsignals=TRUE checkothers=TRUE
MatchedLengths "Schematic Matched Net Lengths_48" [InNet('OCTOSPIM_P1.DQS')] p8: tolerance=0.508 checknetsindiffpair=FALSE checkdiffpairvsdiffpair=TRUE checkxsignals=TRUE checkothers=TRUE
MatchedLengths "Schematic Matched Net Lengths_47" [InNet('SDMMC1.D1')] p9: tolerance=0.508 checknetsindiffpair=FALSE checkdiffpairvsdiffpair=TRUE checkxsignals=TRUE checkothers=TRUE
MatchedLengths "Schematic Matched Net Lengths_46" [InNet('HEXASPI1.IO13')] p10: tolerance=0.508 checknetsindiffpair=FALSE checkdiffpairvsdiffpair=TRUE checkxsignals=TRUE checkothers=TRUE
MatchedLengths "Schematic Matched Net Lengths_45" [InNet('HEXASPI1.IO3')] p11: tolerance=0.508 checknetsindiffpair=FALSE checkdiffpairvsdiffpair=TRUE checkxsignals=TRUE checkothers=TRUE
MatchedLengths "Schematic Matched Net Lengths_44" [InNet('OCTOSPIM_P1.IO4')] p12: tolerance=0.508 checknetsindiffpair=FALSE checkdiffpairvsdiffpair=TRUE checkxsignals=TRUE checkothers=TRUE
MatchedLengths "Schematic Matched Net Lengths_43" [InNet('HEXASPI1.IO14')] p13: tolerance=0.508 checknetsindiffpair=FALSE checkdiffpairvsdiffpair=TRUE checkxsignals=TRUE checkothers=TRUE
MatchedLengths "Schematic Matched Net Lengths_42" [InNet('HEXASPI1.IO8')] p14: tolerance=0.508 checknetsindiffpair=FALSE checkdiffpairvsdiffpair=TRUE checkxsignals=TRUE checkothers=TRUE
MatchedLengths "Schematic Matched Net Lengths_41" [InNet('OCTOSPIM_P1.IO6')] p15: tolerance=0.508 checknetsindiffpair=FALSE checkdiffpairvsdiffpair=TRUE checkxsignals=TRUE checkothers=TRUE
MatchedLengths "Schematic Matched Net Lengths_40" [InNet('HEXASPI1.IO15')] p16: tolerance=0.508 checknetsindiffpair=FALSE checkdiffpairvsdiffpair=TRUE checkxsignals=TRUE checkothers=TRUE
MatchedLengths "Schematic Matched Net Lengths_39" [InNet('HEXASPI1.IO1')] p17: tolerance=0.508 checknetsindiffpair=FALSE checkdiffpairvsdiffpair=TRUE checkxsignals=TRUE checkothers=TRUE
MatchedLengths "Schematic Matched Net Lengths_38" [InNet('SDMMC1.D6')] p18: tolerance=0.508 checknetsindiffpair=FALSE checkdiffpairvsdiffpair=TRUE checkxsignals=TRUE checkothers=TRUE
MatchedLengths "Schematic Matched Net Lengths_37" [InNet('HEXASPI1.IO9')] p19: tolerance=0.508 checknetsindiffpair=FALSE checkdiffpairvsdiffpair=TRUE checkxsignals=TRUE checkothers=TRUE
MatchedLengths "Schematic Matched Net Lengths_36" [InNetClass('HEXADECASPI')] p20: tolerance=0.508 checknetsindiffpair=FALSE checkdiffpairvsdiffpair=TRUE checkxsignals=TRUE checkothers=TRUE
MatchedLengths "Schematic Matched Net Lengths_35" [InNet('HEXASPI1.IO0')] p21: tolerance=0.508 checknetsindiffpair=FALSE checkdiffpairvsdiffpair=TRUE checkxsignals=TRUE checkothers=TRUE
MatchedLengths "Schematic Matched Net Lengths_34" [InNet('SDMMC1.D3')] p22: tolerance=0.508 checknetsindiffpair=FALSE checkdiffpairvsdiffpair=TRUE checkxsignals=TRUE checkothers=TRUE
MatchedLengths "Schematic Matched Net Lengths_33" [InNet('HEXASPI1.IO5')] p23: tolerance=0.508 checknetsindiffpair=FALSE checkdiffpairvsdiffpair=TRUE checkxsignals=TRUE checkothers=TRUE
MatchedLengths "Schematic Matched Net Lengths_32" [InNet('HEXASPI1.DQS0')] p24: tolerance=0.508 checknetsindiffpair=FALSE checkdiffpairvsdiffpair=TRUE checkxsignals=TRUE checkothers=TRUE
MatchedLengths "Schematic Matched Net Lengths_31" [InNet('SDMMC1.D2')] p25: tolerance=0.508 checknetsindiffpair=FALSE checkdiffpairvsdiffpair=TRUE checkxsignals=TRUE checkothers=TRUE
MatchedLengths "Schematic Matched Net Lengths_30" [InNet('OCTOSPIM_P1.IO5')] p26: tolerance=0.508 checknetsindiffpair=FALSE checkdiffpairvsdiffpair=TRUE checkxsignals=TRUE checkothers=TRUE
MatchedLengths "Schematic Matched Net Lengths_29" [InNet('HEXASPI1.DQS1')] p27: tolerance=0.508 checknetsindiffpair=FALSE checkdiffpairvsdiffpair=TRUE checkxsignals=TRUE checkothers=TRUE
MatchedLengths "Schematic Matched Net Lengths_28" [InNet('HEXASPI1.IO7')] p28: tolerance=0.508 checknetsindiffpair=FALSE checkdiffpairvsdiffpair=TRUE checkxsignals=TRUE checkothers=TRUE
MatchedLengths "Schematic Matched Net Lengths_27" [InNet('OCTOSPIM_P1.IO7')] p29: tolerance=0.508 checknetsindiffpair=FALSE checkdiffpairvsdiffpair=TRUE checkxsignals=TRUE checkothers=TRUE
MatchedLengths "Schematic Matched Net Lengths_26" [InNet('OCTOSPIM_P1.IO2')] p30: tolerance=0.508 checknetsindiffpair=FALSE checkdiffpairvsdiffpair=TRUE checkxsignals=TRUE checkothers=TRUE
MatchedLengths "Schematic Matched Net Lengths_25" [InNet('OCTOSPIM_P1.IO1')] p31: tolerance=0.508 checknetsindiffpair=FALSE checkdiffpairvsdiffpair=TRUE checkxsignals=TRUE checkothers=TRUE
MatchedLengths "Schematic Matched Net Lengths_24" [InNet('HEXASPI1.IO12')] p32: tolerance=0.508 checknetsindiffpair=FALSE checkdiffpairvsdiffpair=TRUE checkxsignals=TRUE checkothers=TRUE
MatchedLengths "Schematic Matched Net Lengths_23" [InNet('HEXASPI1.IO6')] p33: tolerance=0.508 checknetsindiffpair=FALSE checkdiffpairvsdiffpair=TRUE checkxsignals=TRUE checkothers=TRUE
MatchedLengths "Schematic Matched Net Lengths_22" [InNet('HEXASPI1.IO10')] p34: tolerance=0.508 checknetsindiffpair=FALSE checkdiffpairvsdiffpair=TRUE checkxsignals=TRUE checkothers=TRUE
MatchedLengths "Schematic Matched Net Lengths_21" [InNet('HEXASPI1.IO4')] p35: tolerance=0.508 checknetsindiffpair=FALSE checkdiffpairvsdiffpair=TRUE checkxsignals=TRUE checkothers=TRUE
MatchedLengths "Schematic Matched Net Lengths_20" [InNet('OCTOSPIM_P1.IO3')] p36: tolerance=0.508 checknetsindiffpair=FALSE checkdiffpairvsdiffpair=TRUE checkxsignals=TRUE checkothers=TRUE
MatchedLengths "Schematic Matched Net Lengths_19" [InNet('SDMMC1.CK')] p37: tolerance=0.508 checknetsindiffpair=FALSE checkdiffpairvsdiffpair=TRUE checkxsignals=TRUE checkothers=TRUE
MatchedLengths "Schematic Matched Net Lengths_18" [InNet('OCTOSPIM_P1.IO0')] p38: tolerance=0.508 checknetsindiffpair=FALSE checkdiffpairvsdiffpair=TRUE checkxsignals=TRUE checkothers=TRUE
MatchedLengths "Schematic Matched Net Lengths_17" [InNet('HEXASPI1.IO11')] p39: tolerance=0.508 checknetsindiffpair=FALSE checkdiffpairvsdiffpair=TRUE checkxsignals=TRUE checkothers=TRUE
MatchedLengths "Schematic Matched Net Lengths_16" [InNetClass('eMMC')] p40: tolerance=0.508 checknetsindiffpair=FALSE checkdiffpairvsdiffpair=TRUE checkxsignals=TRUE checkothers=TRUE
MatchedLengths "Schematic Matched Net Lengths_15" [InNet('SDMMC1.D7')] p41: tolerance=0.508 checknetsindiffpair=FALSE checkdiffpairvsdiffpair=TRUE checkxsignals=TRUE checkothers=TRUE
MatchedLengths "Schematic Matched Net Lengths_14" [InNet('OCTOSPIM_P1.CLK')] p42: tolerance=0.254 checknetsindiffpair=FALSE checkdiffpairvsdiffpair=TRUE checkxsignals=TRUE checkothers=TRUE
MatchedLengths "Schematic Matched Net Lengths_13" [InNet('USBC.HS_P')] p43: tolerance=0.152 checknetsindiffpair=TRUE checkdiffpairvsdiffpair=FALSE checkxsignals=FALSE checkothers=FALSE
MatchedLengths "Schematic Matched Net Lengths_12" [InNet('USBC_CN_HS_P')] p44: tolerance=0.152 checknetsindiffpair=TRUE checkdiffpairvsdiffpair=FALSE checkxsignals=FALSE checkothers=FALSE
MatchedLengths "Schematic Matched Net Lengths_11" [InNet('USB_DEV_HS_CN_N')] p45: tolerance=0 checknetsindiffpair=TRUE checkdiffpairvsdiffpair=FALSE checkxsignals=FALSE checkothers=FALSE
MatchedLengths "Schematic Matched Net Lengths_10" [InNet('USB_DEV_HS_CN_P')] p46: tolerance=0 checknetsindiffpair=TRUE checkdiffpairvsdiffpair=FALSE checkxsignals=FALSE checkothers=FALSE
MatchedLengths "Schematic Matched Net Lengths_9" [InNet('DSI.D1_P')] p47: tolerance=0 checknetsindiffpair=FALSE checkdiffpairvsdiffpair=TRUE checkxsignals=TRUE checkothers=TRUE
MatchedLengths "Schematic Matched Net Lengths_8" [InNet('DSI.CK_P')] p48: tolerance=0 checknetsindiffpair=FALSE checkdiffpairvsdiffpair=TRUE checkxsignals=TRUE checkothers=TRUE
MatchedLengths "Schematic Matched Net Lengths_7" [InNet('USBC.HS_N')] p49: tolerance=0 checknetsindiffpair=TRUE checkdiffpairvsdiffpair=FALSE checkxsignals=FALSE checkothers=FALSE
MatchedLengths "Schematic Matched Net Lengths_6" [InNet('DSI.D0_N')] p50: tolerance=0 checknetsindiffpair=FALSE checkdiffpairvsdiffpair=TRUE checkxsignals=TRUE checkothers=TRUE
MatchedLengths "Schematic Matched Net Lengths_5" [InNet('DSI.D1_N')] p51: tolerance=0 checknetsindiffpair=FALSE checkdiffpairvsdiffpair=TRUE checkxsignals=TRUE checkothers=TRUE
MatchedLengths "Schematic Matched Net Lengths_4" [InNet('USBC_CN_HS_N')] p52: tolerance=0 checknetsindiffpair=TRUE checkdiffpairvsdiffpair=FALSE checkxsignals=FALSE checkothers=FALSE
MatchedLengths "Schematic Matched Net Lengths_3" [InNet('USB_DEV_HS_N')] p53: tolerance=0 checknetsindiffpair=TRUE checkdiffpairvsdiffpair=FALSE checkxsignals=FALSE checkothers=FALSE
MatchedLengths "Schematic Matched Net Lengths_2" [InNet('USB_DEV_HS_P')] p54: tolerance=0 checknetsindiffpair=TRUE checkdiffpairvsdiffpair=FALSE checkxsignals=FALSE checkothers=FALSE
MatchedLengths "Schematic Matched Net Lengths_1" [InNet('DSI.D0_P')] p55: tolerance=0 checknetsindiffpair=FALSE checkdiffpairvsdiffpair=TRUE checkxsignals=TRUE checkothers=TRUE
MatchedLengths "Schematic Matched Net Lengths" [InNet('DSI.CK_N')] p56: tolerance=0 checknetsindiffpair=FALSE checkdiffpairvsdiffpair=TRUE checkxsignals=TRUE checkothers=TRUE
MatchedLengths MatchedLengths_SPI3 [InNetClass('SPI3')] p57: tolerance=6.35 checknetsindiffpair=FALSE checkdiffpairvsdiffpair=TRUE checkxsignals=TRUE checkothers=TRUE
MatchedLengths MatchedLengths_Audio_SAI1 [InxSignalClass('Audio_SAI1')] p58: tolerance=6.35 checknetsindiffpair=FALSE checkdiffpairvsdiffpair=TRUE checkxsignals=TRUE checkothers=TRUE
MatchedLengths MatchedLengths_SDMMC2 [InxSignalClass('SDMMC2')] p59: tolerance=6.35 checknetsindiffpair=FALSE checkdiffpairvsdiffpair=TRUE checkxsignals=TRUE checkothers=TRUE
MatchedLengths MatchedLengths_JTAG_MCU [InxSignalClass('JTAG_MCU')] p60: tolerance=1.27 checknetsindiffpair=FALSE checkdiffpairvsdiffpair=TRUE checkxsignals=TRUE checkothers=TRUE
MatchedLengths MatchedLengths_JTAG_CN11 [InxSignalClass('JTAG_CN11')] p61: tolerance=1.27 checknetsindiffpair=FALSE checkdiffpairvsdiffpair=TRUE checkxsignals=TRUE checkothers=TRUE
MatchedLengths MatchedLengths_JTAG_CN10 [InxSignalClass('JTAG_CN10')] p62: tolerance=1.27 checknetsindiffpair=FALSE checkdiffpairvsdiffpair=TRUE checkxsignals=TRUE checkothers=TRUE
MatchedLengths MatchedLengths_JTAG_STLink [InxSignalClass('JTAG_STLink')] p63: tolerance=2.54 checknetsindiffpair=FALSE checkdiffpairvsdiffpair=TRUE checkxsignals=TRUE checkothers=TRUE
MatchedLengths MatchedLengths_SPI_B [InxSignalClass('SPI_B')] p64: tolerance=6.35 checknetsindiffpair=FALSE checkdiffpairvsdiffpair=TRUE checkxsignals=TRUE checkothers=TRUE
MatchedLengths MatchedLengths_Audio_SAI2 [InxSignalClass('Audio_SAI2')] p65: tolerance=6.35 checknetsindiffpair=FALSE checkdiffpairvsdiffpair=TRUE checkxsignals=TRUE checkothers=TRUE
MatchedLengths MatchedLengths_HexaSPI_Byte0 [InxSignalClass('HexaSPI_Byte0')] p66: tolerance=1.27 checknetsindiffpair=FALSE checkdiffpairvsdiffpair=TRUE checkxsignals=TRUE checkothers=TRUE
MatchedLengths MatchedLengths_HexaSPI_Byte1 [InxSignalClass('HexaSPI_Byte1')] p67: tolerance=1.27 checknetsindiffpair=FALSE checkdiffpairvsdiffpair=TRUE checkxsignals=TRUE checkothers=TRUE
MatchedLengths MatchedLengths_HexaSPI_NCS [InxSignalClass('HexaSPI_NCS')] p68: tolerance=17.78 checknetsindiffpair=FALSE checkdiffpairvsdiffpair=TRUE checkxsignals=TRUE checkothers=TRUE
MatchedLengths MatchedLengths_OctoSPI_Byte0 [InxSignalClass('OctoSPI_Byte0')] p69: tolerance=1.27 checknetsindiffpair=FALSE checkdiffpairvsdiffpair=TRUE checkxsignals=TRUE checkothers=TRUE
MatchedLengths MatchedLengths_OctoSPI_NCS [InxSignalClass('OctoSPI_NCS')] p70: tolerance=19.05 checknetsindiffpair=FALSE checkdiffpairvsdiffpair=TRUE checkxsignals=TRUE checkothers=TRUE
MatchedLengths MatchedLengths_USB [InDifferentialPairClass('USB')] p71: tolerance=0.508 checknetsindiffpair=TRUE checkdiffpairvsdiffpair=FALSE checkxsignals=FALSE checkothers=FALSE
MatchedLengths MatchedLengths_DSI [InDifferentialPairClass('DSI')] p72: tolerance=0.254 checknetsindiffpair=FALSE checkdiffpairvsdiffpair=TRUE checkxsignals=TRUE checkothers=TRUE
MatchedLengths MatchedLengths_eMMC [InxSignalClass('eMMC')] p73: tolerance=1.27 checknetsindiffpair=FALSE checkdiffpairvsdiffpair=TRUE checkxsignals=TRUE checkothers=TRUE
MaxMinImpedance "Schematic Impedance Constraint_57" [InNet('DSI.D1_N')] p1: minimum=95,00 maximum=105,0
MaxMinImpedance "Schematic Impedance Constraint_56" [InNet('DSI.CK_P')] p2: minimum=95,00 maximum=105,0
MaxMinImpedance "Schematic Impedance Constraint_55" [InNet('DSI.D0_N')] p3: minimum=95,00 maximum=105,0
MaxMinImpedance "Schematic Impedance Constraint_54" [InNet('DSI.D1_P')] p4: minimum=95,00 maximum=105,0
MaxMinImpedance "Schematic Impedance Constraint_53" [InNet('DSI.D0_P')] p5: minimum=95,00 maximum=105,0
MaxMinImpedance "Schematic Impedance Constraint_52" [InNet('USB_DEV_HS_CN_N')] p6: minimum=85,00 maximum=95,00
MaxMinImpedance "Schematic Impedance Constraint_51" [InNet('USB_DEV_HS_CN_P')] p7: minimum=85,00 maximum=95,00
MaxMinImpedance "Schematic Impedance Constraint_50" [InNetClass('USB High Speed')] p8: minimum=85,00 maximum=95,00
MaxMinImpedance "Schematic Impedance Constraint_49" [InNet('USB_DEV_HS_N')] p9: minimum=85,00 maximum=95,00
MaxMinImpedance "Schematic Impedance Constraint_48" [InNet('HEXASPI1.NCS')] p10: minimum=50,00 maximum=60,00
MaxMinImpedance "Schematic Impedance Constraint_47" [InNet('HEXASPI1.DQS0')] p11: minimum=50,00 maximum=60,00
MaxMinImpedance "Schematic Impedance Constraint_46" [InNet('HEXASPI1.IO10')] p12: minimum=45,00 maximum=55,00
MaxMinImpedance "Schematic Impedance Constraint_45" [InNet('SDMMC1.D5')] p13: minimum=45,00 maximum=55,00
MaxMinImpedance "Schematic Impedance Constraint_44" [InNet('SDMMC1.D2')] p14: minimum=45,00 maximum=55,00
MaxMinImpedance "Schematic Impedance Constraint_43" [InNet('HEXASPI1.IO0')] p15: minimum=45,00 maximum=55,00
MaxMinImpedance "Schematic Impedance Constraint_42" [InNet('HEXASPI1.DQS1')] p16: minimum=45,00 maximum=55,00
MaxMinImpedance "Schematic Impedance Constraint_41" [InNet('SDMMC1.D6')] p17: minimum=45,00 maximum=55,00
MaxMinImpedance "Schematic Impedance Constraint_40" [InNet('HEXASPI1.IO15')] p18: minimum=45,00 maximum=55,00
MaxMinImpedance "Schematic Impedance Constraint_39" [InNet('HEXASPI1.IO13')] p19: minimum=45,00 maximum=55,00
MaxMinImpedance "Schematic Impedance Constraint_38" [InNet('HEXASPI1.IO14')] p20: minimum=45,00 maximum=55,00
MaxMinImpedance "Schematic Impedance Constraint_37" [InNet('SDMMC1.CK')] p21: minimum=45,00 maximum=55,00
MaxMinImpedance "Schematic Impedance Constraint_36" [InNet('HEXASPI1.IO4')] p22: minimum=45,00 maximum=55,00
MaxMinImpedance "Schematic Impedance Constraint_35" [InNet('HEXASPI1.IO12')] p23: minimum=45,00 maximum=55,00
MaxMinImpedance "Schematic Impedance Constraint_34" [InNet('HEXASPI1.IO6')] p24: minimum=45,00 maximum=55,00
MaxMinImpedance "Schematic Impedance Constraint_33" [InNet('HEXASPI1.IO7')] p25: minimum=45,00 maximum=55,00
MaxMinImpedance "Schematic Impedance Constraint_32" [InNet('HEXASPI1.IO5')] p26: minimum=45,00 maximum=55,00
MaxMinImpedance "Schematic Impedance Constraint_31" [InNet('SDMMC1.CMD')] p27: minimum=45,00 maximum=55,00
MaxMinImpedance "Schematic Impedance Constraint_30" [InNet('SDMMC1.D3')] p28: minimum=45,00 maximum=55,00
MaxMinImpedance "Schematic Impedance Constraint_29" [InNet('SDMMC1.D1')] p29: minimum=45,00 maximum=55,00
MaxMinImpedance "Schematic Impedance Constraint_11" [InNet('SDMMC1.D7')] p30: minimum=45,00 maximum=55,00
MaxMinImpedance "Schematic Impedance Constraint_10" [InNet('HEXASPI1.IO11')] p31: minimum=45,00 maximum=55,00
MaxMinImpedance "Schematic Impedance Constraint_9" [InNet('HEXASPI1.IO8')] p32: minimum=45,00 maximum=55,00
MaxMinImpedance "Schematic Impedance Constraint_8" [InNet('HEXASPI1.IO9')] p33: minimum=45,00 maximum=55,00
MaxMinImpedance "Schematic Impedance Constraint_7" [InNet('HEXASPI1.IO2')] p34: minimum=45,00 maximum=55,00
MaxMinImpedance "Schematic Impedance Constraint_6" [InNetClass('OCTOSPI')] p35: minimum=45,00 maximum=55,00
MaxMinImpedance "Schematic Impedance Constraint_4" [InNet('HEXASPI1.IO3')] p36: minimum=45,00 maximum=55,00
MaxMinImpedance "Schematic Impedance Constraint_3" [InNetClass('HEXADECASPI')] p37: minimum=45,00 maximum=55,00
MaxMinImpedance "Schematic Impedance Constraint_2" [InNet('SDMMC1.D4')] p38: minimum=45,00 maximum=55,00
MaxMinImpedance "Schematic Impedance Constraint" [InNet('HEXASPI1.IO1')] p39: minimum=45,00 maximum=55,00
MaxMinImpedance "Schematic Impedance Constraint_28" [InNet('DSI.D0_P')] p40: minimum=95,00 maximum=105,0
MaxMinImpedance "Schematic Impedance Constraint_27" [InNet('DSI.CK_P')] p41: minimum=95,00 maximum=105,0
MaxMinImpedance "Schematic Impedance Constraint_26" [InNet('DSI.D0_N')] p42: minimum=95,00 maximum=105,0
MaxMinImpedance "Schematic Impedance Constraint_25" [InNet('DSI.CK_N')] p43: minimum=95,00 maximum=105,0
MaxMinImpedance "Schematic Impedance Constraint_24" [InNet('DSI.D1_P')] p44: minimum=95,00 maximum=105,0
MaxMinImpedance "Schematic Impedance Constraint_23" [InNet('DSI.CK_N')] p45: minimum=95,00 maximum=105,0
MaxMinImpedance "Schematic Impedance Constraint_22" [InNet('DSI.D1_N')] p46: minimum=95,00 maximum=105,0
MaxMinImpedance "Schematic Impedance Constraint_21" [InNet('DSI.CK_P')] p47: minimum=95,00 maximum=105,0
MaxMinImpedance "Schematic Impedance Constraint_20" [InNet('DSI.D0_N')] p48: minimum=95,00 maximum=105,0
MaxMinImpedance "Schematic Impedance Constraint_19" [InNet('DSI.D1_P')] p49: minimum=95,00 maximum=105,0
MaxMinImpedance "Schematic Impedance Constraint_18" [InNet('DSI.D0_P')] p50: minimum=95,00 maximum=105,0
MaxMinImpedance "Schematic Impedance Constraint_17" [InNet('DSI.D1_N')] p51: minimum=95,00 maximum=105,0
MaxMinImpedance "Schematic Impedance Constraint_16" [InNet('USB_DEV_HS_CN_N')] p52: minimum=85,00 maximum=95,00
MaxMinImpedance "Schematic Impedance Constraint_15" [InNet('USB_DEV_HS_CN_P')] p53: minimum=85,00 maximum=95,00
MaxMinImpedance "Schematic Impedance Constraint_14" [InNet('USB_DEV_HS_N')] p54: minimum=85,00 maximum=95,00
MaxMinImpedance "Schematic Impedance Constraint_13" [InNet('USB_DEV_HS_P')] p55: minimum=85,00 maximum=95,00
MaxMinImpedance "Schematic Impedance Constraint_12" [InNetClass('USB High Speed')] p56: minimum=85,00 maximum=95,00
MaxMinImpedance "Schematic Impedance Constraint_5" [InNet('SDMMC1.D0')] p57: minimum=45,00 maximum=55,00
MaxMinImpedance "Schematic Impedance Constraint_1" [InNetClass('OCTOSPI')] p58: minimum=45,00 maximum=55,00
MinimumSolderMaskSliver [All] p1: minsoldermaskwidth=0.1
PlaneClearance [All] p1: clearance=0.12
PlaneConnect [All] p1: planeconnectstyle=Relief reliefexpansion=0.508 reliefentries=4 reliefconductorwidth=0.21 reliefairgap=0.21
PolygonConnect PolygonConnect_NO_TH [IsNamedPolygon('NO_TH')] p1: thpad.connectstyle=Relief thpad.reliefconductorwidth=0.25 thpad.reliefentries=4 thpad.polygonreliefangle="90 Angle" thpad.airgapwidth=0.25 smdpad.connectstyle=Direct smdpad.reliefconductorwidth=0.254 smdpad.reliefentries=4 smdpad.polygonreliefangle="90 Angle" smdpad.airgapwidth=0.254 via.connectstyle=Direct via.reliefconductorwidth=0.254 via.reliefentries=4 via.polygonreliefangle="90 Angle" via.airgapwidth=0.254
PolygonConnect [All] p2: thpad.connectstyle=Relief thpad.reliefconductorwidth=0.2 thpad.reliefentries=4 thpad.polygonreliefangle="90 Angle" thpad.airgapwidth=0.2 smdpad.connectstyle=Relief smdpad.reliefconductorwidth=0.2 smdpad.reliefentries=4 smdpad.polygonreliefangle="90 Angle" smdpad.airgapwidth=0.2 via.connectstyle=Direct via.reliefconductorwidth=0.2 via.reliefentries=4 via.polygonreliefangle="90 Angle" via.airgapwidth=0.2
RoomDefinition U_MECHANICAL [InComponentClass('U_MECHANICAL')] p1: confinementstyle=ConfineIn formatcopy=TRUE lockcomponents=FALSE outline 53.175,7.25 53.175,21.875 67.65,21.875 67.65,7.25
RoutingLayers "Schematic Routing Layers_5" [InNetClass('OCTOSPI')] p1: top layer_v5=TRUE mid layer 1_v5=TRUE mid layer 2_v5=TRUE mid layer 3_v5=TRUE mid layer 4_v5=TRUE bottom layer_v5=TRUE
RoutingLayers "Schematic Routing Layers_4" [InNetClass('HEXADECASPI')] p2: top layer_v5=TRUE mid layer 1_v5=TRUE mid layer 2_v5=TRUE mid layer 3_v5=TRUE mid layer 4_v5=TRUE bottom layer_v5=TRUE
RoutingLayers "Schematic Routing Layers_3" [InNetClass('HEXASPI')] p3: top layer_v5=TRUE mid layer 1_v5=TRUE mid layer 2_v5=TRUE mid layer 3_v5=TRUE mid layer 4_v5=TRUE bottom layer_v5=TRUE
RoutingLayers "Schematic Routing Layers_1" [InNetClass('USB High Speed')] p4: top layer_v5=TRUE mid layer 1_v5=TRUE mid layer 2_v5=TRUE mid layer 3_v5=TRUE mid layer 4_v5=TRUE bottom layer_v5=TRUE
RoutingLayers "Schematic Routing Layers_2" [InNetClass('USB High Speed')] p5: top layer_v5=TRUE mid layer 1_v5=TRUE mid layer 2_v5=TRUE mid layer 3_v5=TRUE mid layer 4_v5=TRUE bottom layer_v5=TRUE
RoutingLayers "Schematic Routing Layers" [InNetClass('OCTOSPI')] p6: top layer_v5=TRUE mid layer 1_v5=TRUE mid layer 2_v5=TRUE mid layer 3_v5=TRUE mid layer 4_v5=TRUE bottom layer_v5=TRUE
RoutingLayers [All] p7: top layer_v5=TRUE mid layer 1_v5=TRUE mid layer 2_v5=TRUE mid layer 3_v5=TRUE mid layer 4_v5=TRUE bottom layer_v5=TRUE
RoutingVias [All] p1: holewidth=0.2 width=0.45 viastyle="Through Hole" minholewidth=0.1 minwidth=0.25 maxholewidth=0.2 maxwidth=0.45
SilkToSilkClearance [All] p1: silktosilkclearance=0.2
SilkToSolderMaskClearance [IsPad] p1: minsilkscreentomaskgap=0.2 clearancetoexposedcopper=TRUE
SolderMaskExpansion [All] p1: expansion=0.102 istentingtop=FALSE
Width Width_BGA_MCU_HexaSPI [WithinRoom('RoomDefinition')and TouchesRoom('RoomDefinition')] p1: maxlimit=10 minlimit=0.08 preferedwidth=0.1
Width Width_eMMC [WithinRoom('RoomDefinition_2')and TouchesRoom('RoomDefinition_2')] p2: maxlimit=10 minlimit=0.08 preferedwidth=0.12
Width Width_BGA_STLink [WithinRoom('RoomDefinition_1')and TouchesRoom('RoomDefinition_1')] p3: maxlimit=10 minlimit=0.08 preferedwidth=0.1
Width Width_50Ohms [InNetClass('50Ohms')] p4: maxlimit=0.254 minlimit=0.09 preferedwidth=0.1 toplayer_minwidth=0.1 toplayer_maxwidth=0.12 toplayer_prefwidth=0.12 midlayer1_minwidth=0.1 midlayer2_maxwidth=0.09 midlayer2_prefwidth=0.09 midlayer3_maxwidth=0.09 midlayer3_prefwidth=0.09 midlayer4_minwidth=0.1 bottomlayer_minwidth=0.1 bottomlayer_maxwidth=0.12 bottomlayer_prefwidth=0.12 minimp=50.000000 maximp=50.000000 favimp=50.000000
Width Width_Alim [InNetClass('Alim')] p5: maxlimit=10 minlimit=0.08 preferedwidth=0.25 toplayer_minwidth=0.15 midlayer1_minwidth=0.2 midlayer2_minwidth=0.2 midlayer3_minwidth=0.2 midlayer4_minwidth=0.2 minimp=50.000000 maximp=50.000000 favimp=50.000000
Width [All] p6: maxlimit=10 minlimit=0.09 preferedwidth=0.12 minimp=50.000000 maximp=50.000000 favimp=50.000000
20 further rules are at their usual default settings.

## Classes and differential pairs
component class U_MEMS: C18 C21 C113 C114 R7 R8 R9 R56 SB4 SB5 SB12 SB13 TP3 U7 U18
component class U_HEXADECASPI_PSRAM: C84 C88 C97 C99 R52 SB47 U34
net class Audio: AOUTA AOUTB MIC
net class Diff: DSI.CK_N DSI.CK_P DSI.D0_N DSI.D0_P DSI.D1_N DSI.D1_P USB_DEV_HS_CN_N USB_DEV_HS_CN_P USB_DEV_HS_N USB_DEV_HS_P USBC.HS_N USBC.HS_P USBC_CN_HS_N USBC_CN_HS_P
net class SPI3: PG9 PG10 PG11 PG15
net class OSC: NetC14_1 NetC33_1 PC14-OSC32_IN PC15-OSC32_OUT PH0-OSC_IN PH1-OSC_OUT
net class Alim: 1V8 1V8_AUDIO 1V8_LCD 3V3 3V3_LCD 3V3_STLK 5V 5V_LCD 5V_STLK 5V_UCPD 5V_USB_CHGR 5V_VIN GND V11 VBAT VBUS_SENSE VBUSc VCC_eMMC VCCQ_eMMC VDD VDD_HEXASPI VDD_LCD VDD_MCU VDD_OCTOSPI VDD_SMPS VDD_USB VDDA VDDMCU_SMPS VIN VL_AUDIO VLX_SMPS VREFP
net class 50Ohms: HEXASPI1.CLK HEXASPI1.DQS0 HEXASPI1.DQS1 HEXASPI1.IO0 HEXASPI1.IO1 HEXASPI1.IO2 HEXASPI1.IO3 HEXASPI1.IO4 HEXASPI1.IO5 HEXASPI1.IO6 HEXASPI1.IO7 HEXASPI1.IO8 HEXASPI1.IO9 HEXASPI1.IO10 HEXASPI1.IO11 HEXASPI1.IO12 HEXASPI1.IO13 HEXASPI1.IO14 HEXASPI1.IO15 HEXASPI1.NCS NetCN9_4 NetCN9_6 NetCN10_13 NetCN10_15 NetCN10_17 NetCN10_19 NetR12_1 NetR121_1 OCTOSPIM_P1.CLK OCTOSPIM_P1.DQS OCTOSPIM_P1.IO0 OCTOSPIM_P1.IO1 OCTOSPIM_P1.IO2 OCTOSPIM_P1.IO3 OCTOSPIM_P1.IO4 OCTOSPIM_P1.IO5 OCTOSPIM_P1.IO6 OCTOSPIM_P1.IO7 OCTOSPIM_P1.NCS PA6 PB0 PB1 PB3 PB4 PB10 PB11 PB12 PB13 PB14 PB15 PD0 PD1 PD3 PD4 PD6 PD7 PD9 PD10 PD11 PD12 PE2 PE4 PE5 PE6 PE7 PF0 PF1 PF5 PF12 PF13 PF14 PF15 PG0 PG7 PG8 PG9 PG10 PG11 PG15 SAI1.SD_B SDMMC1.CK SDMMC1.CMD SDMMC1.D0 SDMMC1.D1 SDMMC1.D2 SDMMC1.D3 SDMMC1.D4 SDMMC1.D5 SDMMC1.D6 SDMMC1.D7 SPI_CLK SPI_MOSI T.JTDI T.SWCLK T.SWDIO T.SWO T_SWCLKa T_SWDIO_IN T_SWDIOa T_SWOa
differential pair class USB: USB_DEV_HS USB_DEV_HS_CN USBC.HS USBC_CN_HS
differential pair class DSI: DSI.CK DSI.D0 DSI.D1
net class eMMC: SDMMC1.CK SDMMC1.CMD SDMMC1.D0 SDMMC1.D1 SDMMC1.D2 SDMMC1.D3 SDMMC1.D4 SDMMC1.D5 SDMMC1.D6 SDMMC1.D7
component class U_AUDIO: C1 C2 C3 C4 C5 C6 C7 C8 C9 C10 C11 C12 C13 C14 C15 C16 C17 C19 C20 CN1 CN6 R1 R2 R3 R4 R5 R6 R10 R11 R12 R13 R14 R15 SB1 SB2 SB3 U1 U2 U3 U4 U5 U6
component class U_BOARD_POWER: C115 C116 C117 C118 C126 C129 C130 C131 C132 C133 C134 C135 C136 C149 JP1 JP2 JP3 JP4 L6 L7 LD1 LD2 Q2 R57 R58 R59 R60 R61 R62 R63 R64 R65 R66 R77 R79 R80 R81 R82 R83 R84 R85 R86 R87 R88 R89 R90 R91 R92 R93 R103 R109 TP1 TP2 TP13 TP22 TP23 U19 U20 U23 U24 U28
component class U_DSI_LCD: C22 C23 C24 C119 C120 C121 C122 C123 C124 CN2 L4 L5 R16 R17 R18 R19 R69 R70 R71 R72 R73 R74 R75 R76 R78 SB14 SB15 SB16 SB17 SB18 SB19 SB49 SB50 SB51 SB52 SB53 T1 T2 T3 T4
component class U_eMMC: C55 C57 C58 C66 C67 C69 C70 C137 C139 R30 R95 R96 R97 R98 R99 R100 R101 R102 R111 R112 R113 R114 SB39 SB41 SB44 U26 U27
component class U_EXTENSION_CONNECTORS: C25 C125 CN9 CN10 R28 R29 SB6 SB7 SB8 SB9 SB10 SB11 SB20 SB21 SB22 SB23 SB24 SB25 SB26 SB33 SB45 SB48 SB54 SB55 SB56
component class U_MCU_CLOCK_&_USER_INTERFACE: B1 B2 C28 C29 C32 C33 C127 C128 LD3 LD4 Q3 Q4 R26 R27 R55 R67 R68 R104 R105 R106 R107 R116 R125 SW1 U8 U21 X1 X3
component class U_MCU_IO: SB34 SB38 SB40 SB42 SB43 SB46 SB57 SB58 SB59 TP7 TP8 TP9 TP10 TP11 TP12 TP14 TP15 TP16 TP17 TP18 TP19 TP20 TP21 TP24 TP25 TP26 TP27 TP28 TP29 TP30 TP31 U25
component class U_MCU_PWR: C36 C37 C38 C39 C40 C41 C42 C43 C44 C45 C46 C47 C48 C49 C50 C51 C52 C53 C54 C56 C60 C61 C62 C63 C64 C65 C68 C138 C140 L1 L2 L3 L8 SB29 SB30 SB31 SB32 SB35 SB36 SB37
component class U_MECHANICAL: H1 H2 H3 H4 H5 HW1 HW2 HW3 HW8 HW9 HW10 HW17 HW18 HW19 HW20 HW21 HW22
component class U_OCTOSPI_FLASH: C26 C27 C30 C31 C34 C35 R20 R21 R22 R23 R24 R25 SB27 TP4 TP5 TP6 U22
component class U_ST_LINK_V3E: C73 C74 C75 C76 C77 C78 C80 C82 C83 C85 C86 C87 C89 C91 C92 C95 C96 C98 C100 C101 C102 C103 C104 C106 C107 C108 C109 C110 C111 C112 C141 C142 C143 C144 C145 C146 C148 CN3 CN5 CN11 CN12 D1 D2 D3 JP5 JP6 LD5 LD6 R33 R34 R42 R44 R45 R46 R49 R50 R51 R53 R54 R108 R110 R115 R117 R118 R119 R121 R122 R123 R124 R126 R127 R130 R131 SB28 U10 U13 U14 U15 U16 U17 U29 U30 U31 U32 U33 X2
component class U_USBHS_TYPEC: C59 C71 C72 C79 C81 C90 C93 C94 C105 C147 CN4 D4 LD7 Q1 Q5 R31 R32 R35 R36 R37 R38 R39 R40 R41 R43 R47 R48 R120 R128 R129 U9 U11 U12 U35
net class HEXASPI: HEXASPI1.CLK HEXASPI1.DQS0 HEXASPI1.DQS1 HEXASPI1.IO0 HEXASPI1.IO1 HEXASPI1.IO2 HEXASPI1.IO3 HEXASPI1.IO4 HEXASPI1.IO5 HEXASPI1.IO6 HEXASPI1.IO7 HEXASPI1.IO8 HEXASPI1.IO9 HEXASPI1.IO10 HEXASPI1.IO11 HEXASPI1.IO12 HEXASPI1.IO13 HEXASPI1.IO14 HEXASPI1.IO15 HEXASPI1.NCS
net class OCTOSPI: NetR23_1 OCTOSPIM_P1.CLK OCTOSPIM_P1.DQS OCTOSPIM_P1.IO0 OCTOSPIM_P1.IO1 OCTOSPIM_P1.IO2 OCTOSPIM_P1.IO3 OCTOSPIM_P1.IO4 OCTOSPIM_P1.IO5 OCTOSPIM_P1.IO6 OCTOSPIM_P1.IO7 OCTOSPIM_P1.NCS
net class "USB High Speed": USB_DEV_HS_CN_N USB_DEV_HS_CN_P USB_DEV_HS_N USB_DEV_HS_P USBC.HS_N USBC.HS_P USBC_CN_HS_N USBC_CN_HS_P
net class Audio_SAI1: PE2 PE4 PE5 PE6 PE7 SAI1.SD_B
net class Audio_SAI2: NetCN10_13 NetCN10_15 PD9 PD10 PD11 PD12
net class SPI: NetCN10_13 NetCN10_15 NetCN10_17 NetCN10_19 PB12 PB13 PD3 PD4
net class SDMMC2: NetCN9_4 NetCN9_6 PB3 PB4 PB14 PB15 PD6 PD7
net class JTAG: NetR121_1 PB3 T.JTDI T.SWCLK T.SWDIO T.SWO T_SWCLKa T_SWDIO_IN T_SWDIOa T_SWOa
net class DSI: DSI.CK_N DSI.CK_P DSI.D0_N DSI.D0_P DSI.D1_N DSI.D1_P
net class VREFP_AGND_VDDA: AGND VDDA VREFP
differential pair DSI.CK: +DSI.CK_P -DSI.CK_N
differential pair DSI.D0: +DSI.D0_P -DSI.D0_N
differential pair DSI.D1: +DSI.D1_P -DSI.D1_N
differential pair USB_DEV_HS_CN: +USB_DEV_HS_CN_P -USB_DEV_HS_CN_N
differential pair USB_DEV_HS: +USB_DEV_HS_P -USB_DEV_HS_N
differential pair USBC.HS: +USBC.HS_P -USBC.HS_N
differential pair USBC_CN_HS: +USBC_CN_HS_P -USBC_CN_HS_N

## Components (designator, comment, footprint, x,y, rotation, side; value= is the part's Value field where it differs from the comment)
B1 "SW_BLUE_KSC721JLFS" SWI_C&K_KSC721JLFS_BLUE 84.25,91.45 r180 top value=KSC721JLFS
B2 "SW_BLACK_KSC321JLFS" SWI_C&K_KSC321JLFS_BLACK 84.25,81 r0 top value=KSC321JLFS
C1 "Capacitor" C0402 45.65,104.05 r270 top value=100nF
C2 "Capacitor" C0402 40.4,103.875 r90 top value=100nF
C3 "Capacitor" C0603 32.075,98.175 r270 top value=150pF
C4 "Capacitor" C0603 33.45,98.175 r270 top value=150pF
C5 "Capacitor" C0402 34.75,97.85 r270 top value=100nF
C6 "Capacitor" C0402 36.875,97.85 r270 top value=1uF
C7 "Capacitor" C0603 38.725,96.25 r180 top value=10uF
C8 "Capacitor" C0402 28.65,95.125 r180 top value=100nF
C9 "Capacitor" C0402 38.4,94.95 r180 top value=1uF
C10 "Capacitor" C0402 38.4,94.025 r180 top value=1uF
C11 "Capacitor" C0402 28.7,93.5 r90 top value=1uF
C12 "Capacitor" C0402 29.5,93.5 r90 top value=100nF
C13 "Capacitor" C0402 38.4,93.1 r180 top value=100nF
C14 "Capacitor" C0402 38.4,91.825 r180 top value=22nF
C15 "Capacitor" C0402 38.4,90.5 r180 top value=22nF
C16 "Capacitor" C0603 37.775,88.8 r90 top value=1uF
C17 "Capacitor" C0603 35.175,89.025 r180 top value=1uF
C18 "Capacitor" C0603 2.125,87.75 r90 top value=100nF
C19 "Capacitor" C0402 34.75,87.9 r180 top value=1uF
C20 "Capacitor" C0402 34.75,87.05 r180 top value=100nF
C21 "Capacitor" C0603_H0P8 4.85,82.6 r0 top value=4.7uF
C22 "Capacitor" C0402 43.4,76.571 r180 top value=100nF
C23 "Capacitor" C0402 47.975,75.171 r90 top value=100nF
C24 "Capacitor" C0402 48.8,75.171 r90 top value=100nF
C25 "Capacitor" C0603 27.4,74.9 r270 top value=100nF
C26 "Capacitor" C0603 51.225,53.925 r180 top value=4.7uF
C27 "Capacitor" C0402 51.225,52.85 r180 top value=100nF
C28 "Capacitor" C0402 46.65,52.05 r90 top value=100nF
C29 "Capacitor" C0402 44.1,51.9 r180 top value=100nF
C30 "Capacitor" C0402 55.55,49.625 r270 top value=100nF
C31 "Capacitor" C0603 56.675,49.3 r270 top value=4.7uF
C32 "Capacitor" C0402 41.125,48.025 r180 top value=8.2pF
C33 "Capacitor" C0402 43.075,48.025 r0 top value=8.2pF
C34 "Capacitor" C0402 50.225,47.5 r0 top value=100nF
C35 "Capacitor" C0603 50.225,46.4 r0 top value=4.7uF
C36 "Capacitor" C0402 33.25,40.85 r0 top value=100nF
C37 "Capacitor" C0402 42.125,39.1 r270 top value=100nF
C38 "Capacitor" C0402 37.425,38.925 r270 top value=100nF
C39 "Capacitor" C0402 38.225,38.925 r270 top value=100nF
C40 "Capacitor" C0402 39.025,38.925 r270 top value=100nF
C41 "Capacitor" C0402 43.95,38.45 r180 top value=1uF
C42 "Capacitor" C0402 34.975,38.4 r0 top value=100nF
C43 "Capacitor" C0402 43.95,37.65 r180 top value=100nF
C44 "Capacitor" C0402 34.175,36.85 r0 top value=2.2uF
C45 "Capacitor" C0402 43.95,36.85 r180 top value=100nF
C46 "Capacitor" C0402 34.175,36.05 r0 top value=100nF
C47 "Capacitor" C0402 42.05,36.05 r180 top value=100nF
C48 "Capacitor" C0402 43.95,36.05 r180 top value=1uF
C49 "Capacitor" C0402 42.05,35.25 r180 top value=100nF
C50 "Capacitor" C0402 34.175,35.225 r0 top value=100nF
C51 "Capacitor" C0402 42.05,34.45 r180 top value=100nF
C52 "Capacitor" C0603_H0P8 44.2,33.8 r0 top value=10uF
C53 "Capacitor" C0402 34.175,33.7 r0 top value=100nF
C54 "Capacitor" C0402 42.05,33.65 r180 top value=10uF
C55 "Capacitor" C0402 18.025,33.425 r180 top value=100nF
C56 "Capacitor" C0402 43.9,32.775 r0 top value=100nF
C57 "Capacitor" C0603 14.8,31.3 r270 top value=2.2uF
C58 "Capacitor" C0402 15.85,31.525 r270 top value=100nF
C59 "Capacitor" C0603 67.225,31.075 r180 top value=10pF
C60 "Capacitor" C0402 35.725,30.625 r90 top value=100nF
C61 "Capacitor" C0402 38.125,30.625 r90 top value=100nF
C62 "Capacitor" C0402 38.925,30.625 r90 top value=100nF
C63 "Capacitor" C0402 39.725,30.625 r90 top value=100nF
C64 "Capacitor" C0402 40.525,30.625 r90 top value=100nF
C65 "Capacitor" C0402 36.925,31.025 r0 top value=100nF
C66 "Capacitor" C0402 17.8,30.55 r90 top value=100nF
C67 "Capacitor" C0603 19.725,29.7 r270 top value=2.2uF
C68 "Capacitor" C0402 36.925,30.225 r0 top value=4.7uF
C69 "Capacitor" C0402 18.085,28.286 r90 top value=100nF
C70 "Capacitor" C0402 18.383,26.338 r0 top value=100nF
C71 "Capacitor" C0402 23.575,22.425 r180 top value=100nF
C72 "Capacitor" C0402 25.525,22.425 r180 top value=100nF
C73 "Capacitor" C0402 60.375,21.075 r90 top value=100nF
C74 "Capacitor" C0402 61.275,21.075 r90 top value=100nF
C75 "Capacitor" C0402 57.5,21.075 r90 top value=100nF
C76 "Capacitor" C0402 58.45,21.075 r90 top value=100nF
C77 "Capacitor" C0402 59.375,21.075 r90 top value=100nF
C78 "Capacitor" C0603 67.2,18.85 r180 top value=2.2uF
C79 "Capacitor" C0402 21.9,18.75 r180 top value=330pF
C80 "Capacitor" C0402 54.175,18.5 r180 top value=100nF
C81 "Capacitor" C0603 21.875,17.65 r180 top value=100nF
C82 "Capacitor" C0402 68.525,17.575 r180 top value=20pF
C83 "Capacitor" C0402 54.2,17.525 r180 top value=100nF
C84 "Capacitor" C0603_H0P8 39.7,17.175 r0 top value=10uF
C85 "Capacitor" C0402 51.375,16.625 r0 top value=100nF
C86 "Capacitor" C0402 54.2,16.575 r180 top value=100nF
C87 "Capacitor" C0402 66.8,16.45 r0 top value=100nF
C88 "Capacitor" C0402 39.7,16.125 r0 top value=100nF
C89 "Capacitor" C0402 66.8,15.575 r0 top value=100nF
C90 "Capacitor" C0402 21.55,15.175 r180 top value=330pF
C91 "Capacitor" C0402 66.8,14.7 r0 top value=100nF
C92 "Capacitor" C0402 54.2,14.275 r180 top value=100nF
C93 "Capacitor" C0402 22.35,13 r270 top value=100pF
C94 "Capacitor" C0402 23.55,12.991 r270 top value=1uF
C95 "Capacitor" C0603 67.125,12.55 r180 top value=2.2uF
C96 "Capacitor" C0402 69.625,12.775 r180 top value=10nF
C97 "Capacitor" C0603_H0P8 43.35,11.825 r90 top value=10uF
C98 "Capacitor" C0402 73.3,12.375 r180 top value=1uF
C99 "Capacitor" C0402 42.275,11.5 r90 top value=100nF
C100 "Capacitor" C0402 73.3,11.5 r180 top value=100nF
C101 "Capacitor" C0402 66.8,11.4 r0 top value=100nF
C102 "Capacitor" C0402 67,10.05 r270 top value=1uF
C103 "Capacitor" C0402 67.875,10.05 r270 top value=100nF
C104 "Capacitor" C0402 54.2,10.125 r180 top value=100nF
C105 "Capacitor" C0603 15.375,9.35 r180 top value=100nF
C106 "Capacitor" C0603 53.875,9.025 r0 top value=4.7uF
C107 "Capacitor" C0402 58.775,8.5 r270 top value=100nF
C108 "Capacitor" C0402 59.75,8.5 r270 top value=100nF
C109 "Capacitor" C0402 60.675,8.5 r270 top value=100nF
C110 "Capacitor" C0603 61.775,8.175 r90 top value=2.2uF
C111 "Capacitor" C0402 55.55,8.45 r90 top value=1uF
C112 "Capacitor" C0402 62.8,6.475 r0 top value=100pF
C113 "Capacitor" C0603 12.05,107.169 r90 bottom value=100nF
C114 "Capacitor" C0603 10.675,107.169 r270 bottom value=2.2uF
C115 "Capacitor" C0603_H0P8 77.9,98.25 r90 bottom value=10uF
C116 "Capacitor" C0603_H0P8 80.4,98.225 r270 bottom value=10uF
C117 "Capacitor" C0603_H0P8 71.225,97.475 r90 bottom value=10uF
C118 "Capacitor" C0603_H0P8 82.6,95.875 r0 bottom value=10uF
C119 "Cap_POL_TANA" CPOL_TAJ-A_1206_H180 50.6,83.996 r180 bottom value=10uF
C120 "Capacitor" C0402 51.4,82.421 r0 bottom value=100nF
C121 "Capacitor" C0603 42.05,74.971 r90 bottom value=100pF
C122 "Capacitor" C0603 53.6,69.171 r180 bottom value=100pF
C123 "Capacitor" C0603 49.9,69.171 r180 bottom value=100pF
C124 "Capacitor" C0603 44.925,67.246 r0 bottom value=100pF
C125 "Capacitor" C0603 28.475,54.225 r90 bottom value=100nF
C126 "Capacitor" C0402 68.472,45.841 r0 bottom value=3.3nF
C127 "Capacitor" C0402 32.775,45 r0 bottom value=3.3pF
C128 "Capacitor" C0402 30.575,45 r180 bottom value=3.3pF
C129 "Capacitor" C1206_H1P6 72.172,41.066 r90 bottom value=10uF
C130 "Capacitor" C0402 71.225,44.5 r270 bottom value=100nF
C131 "Capacitor" C0603_H0P8 81.3,41.25 r270 bottom value=22uF
C132 "Capacitor" C0603_H0P8 79.875,41.25 r90 bottom value=22uF
C133 "Capacitor" C0603_H0P8 67.175,40.175 r180 bottom value=22uF
C134 "Capacitor" C0603_H0P8 67.197,38.841 r180 bottom value=22uF
C135 "Capacitor" C0402 85.65,37.575 r180 bottom value=100nF
C136 "Capacitor" C1206_H1P6 82.1,36.35 r0 bottom value=10uF
C137 "Capacitor" C0603 23.625,34.05 r270 bottom value=2.2uF
C138 "Capacitor" C0402 46.325,32.05 r270 bottom value=20pF
C139 "Capacitor" C0402 23.575,31.925 r90 bottom value=100nF
C140 "Capacitor" C0402 46.325,29.685 r90 bottom value=2.2uF
C141 "Capacitor" C0402 74.05,26.525 r180 bottom value=1uF
C142 "Capacitor" C0402 73.15,21.85 r0 bottom value=1uF
C143 "Capacitor" C0402 60.3,18.975 r0 bottom value=100nF
C144 "Capacitor" C0402 64.65,18.525 r270 bottom value=100nF
C145 "Capacitor" C0402 64.65,16.325 r270 bottom value=100nF
C146 "Capacitor" C0402 58.85,14.2 r90 bottom value=100nF
C147 "Capacitor" C0402 20.028,11.9 r0 bottom value=470pF
C148 "Capacitor" C0402 52.15,9.4 r270 bottom value=100nF
C149 "Capacitor" C0402 88.175,40.2 r270 bottom value=3.3nF
CN1 "Socket 10x2" CON_FCI_20021311-XXX20XXLF 45,107.185 r0 top
CN2 "Socket QSH-030-01-F-D-A_DSI_LCD" CON_SAMTEC_QSH-030-01-F-D-A_NO-LCD-MB1835 12.079,45.479 r0 top value="Socket 30x2"
CN3 "Tag-10-C" CON_TAG-C_TC2050-IDC-NL 86.665,17.395 r270 top value="Header 5x2"
CN4 "USB_TYPE_C_Receptacle_317JD24BZTF3K3C3" CON_USB-TYPEC_COXOC_317JD24BZTF3K3C3 24.824,0 r0 top value=USB_C_317JD24BZTF3K3C3
CN5 "USB_uB_105017.0001" CON_USBMICROB_MOLEX_105017-0001_H2P90 66.1,0.025 r0 top value=USB_uB_105017-0001
CN6 "Jack_PJ3028B-3_4P" CON_PHONE-JACK-3P5_HY_PJ3028B 56.525,110 r270 bottom value="Jack_ Socket-Stereo_PJ3028B-3_4P"
CN9 "Socket 15x2" CON_SAMTEC_SSW-115-21-F-D 67.77,71.344 r270 bottom locked
CN10 "Socket 19x2" CON_SAMTEC_SSW-119-21-F-D 22.05,68.804 r270 bottom locked
CN11 "Header 7x2_MIPI10_on_STDC14" CON_STDC14_Receiver_MEDIUM__3D_FTSH-105-01-L-DV-K 59.425,25.825 r0 bottom value="Header 5x2"
CN12 "Header 4x1" CON_SAMTEC_TSW-104-07-G-S 54.925,1.875 r0 bottom
D1 "BAT60JFILM" DIO_SOD323 72.5,28.85 r270 top
D2 "BAT60JFILM" DIO_SOD323 69.95,28.85 r270 top
D3 "BAT60JFILM" DIO_SOD323 75.025,28.85 r270 top
D4 "SCHOTTKY_1A_2K" DIO_SOD523_1A_2K 21.9,16.3 r180 top value=BAT54KFILM
H1 "POSITION HOLE" PTH_350_700_H-12 5,105 r0 top value=PTH
H2 "POSITION HOLE" PTH_350_700_H-12 85.2,104.975 r0 top value=PTH
H3 "POSITION HOLE" PTH_450_900 83.241,72.252 r0 top
H4 "POSITION HOLE" PTH_350_500 58.519,53.51 r0 top value=PTH
H5 "POSITION HOLE" PTH_350_500 15.579,48.979 r0 top value=PTH
H6 "POSITION HOLE" PTH_350_700_H-12 5,5 r0 top value=PTH
H7 "POSITION HOLE" PTH_350_700_H-12 85,5 r0 top value=PTH
HW1 "STICKER_PRODUCT" STICKER_PRODUCT_25X5 62.3,93.575 r180 top value="Sticker product"
HW2 "STICKER_ES" STICKER_ES_6X6 5.175,63.925 r270 bottom value="Sticker ES"
HW3 "STICKER_BOARD" STICKER_BOARD_25X9 5.15,47.425 r90 bottom value="Sticker board"
JP1 "Jumper_Header 2x1 Fitted" CON_SAMTEC_TSW-102-07-G-S 82.6,49.15 r0 bottom value="Header 2x1"
JP2 "Jumper_Header 2x1 Fitted" CON_SAMTEC_TSW-102-07-G-S 62.225,36.35 r0 bottom value="Header 2x1"
JP3 "Jumper_Header 2x1 Fitted" CON_SAMTEC_TSW-102-07-G-S 56.125,36.325 r180 bottom value="Header 2x1"
JP4 "Jumper_Header 4x2 Fitted 1-2" CON_SAMTEC_TSW-104-07-X-D 73.775,33.525 r180 bottom value="Header 4x2"
JP5 "Jumper_Header 2x1 Fitted" CON_SAMTEC_TSW-102-07-G-S 50.35,18.975 r180 bottom value="Header 2x1"
JP6 "Jumper_Header 2x1" CON_SAMTEC_TSW-102-07-G-S 50.175,11.125 r270 bottom value="Header 2x1"
L1 "Inductor" IND_0402_MURATA_BLM15H_H0P5 41.1,39.125 r270 top value="470R @ 100MHz"
L2 "Inductor" IND_0402_MURATA_BLM15H_H0P5 44,35.05 r180 top value="470R @ 100MHz"
L3 "BEAD" FIL_0603_H0P65 48.8,31.8 r90 top value="26R @ 100Mhz"
L4 "BEAD" L0603 53.2,81.425 r90 bottom value="600R @ 100MHz"
L5 "BEAD" L0603 49.425,81.421 r90 bottom value="600R @ 100MHz"
L6 "INDUCTOR_POWER_WINDING" IND_COILCRAFT_XGL4020 82.175,44.875 r90 bottom value=2.2uH
L7 "INDUCTOR_POWER_WINDING" IND_COILCRAFT_XGL4020 63.472,41.241 r180 bottom value=3.3uH
L8 "Inductor" L0805_H0P9 47.7,30.9 r90 bottom value=2.2uH
LD1 "LED_green" LED_0603_OSRAM_LG-Q396-PS-35_GREEN_1A2K_H0P4 88.475,60.35 r270 top locked value=GREEN
LD2 "LED_green" LED_0603_OSRAM_LG-Q396-PS-35_GREEN_1A2K_H0P4 88.75,29.8 r270 top locked value=GREEN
